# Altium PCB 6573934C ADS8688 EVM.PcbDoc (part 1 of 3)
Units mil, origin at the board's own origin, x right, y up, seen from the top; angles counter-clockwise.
Board outline 4100 x 2700 mil, 6 copper layers (L1_Analog, L2_GND, L3_AnalogPower, L4_DigPower, L5_GND, L6_Digital), stack 58.4 mil thick; 282 components, 187 nets, 719 pads, 318 vias.
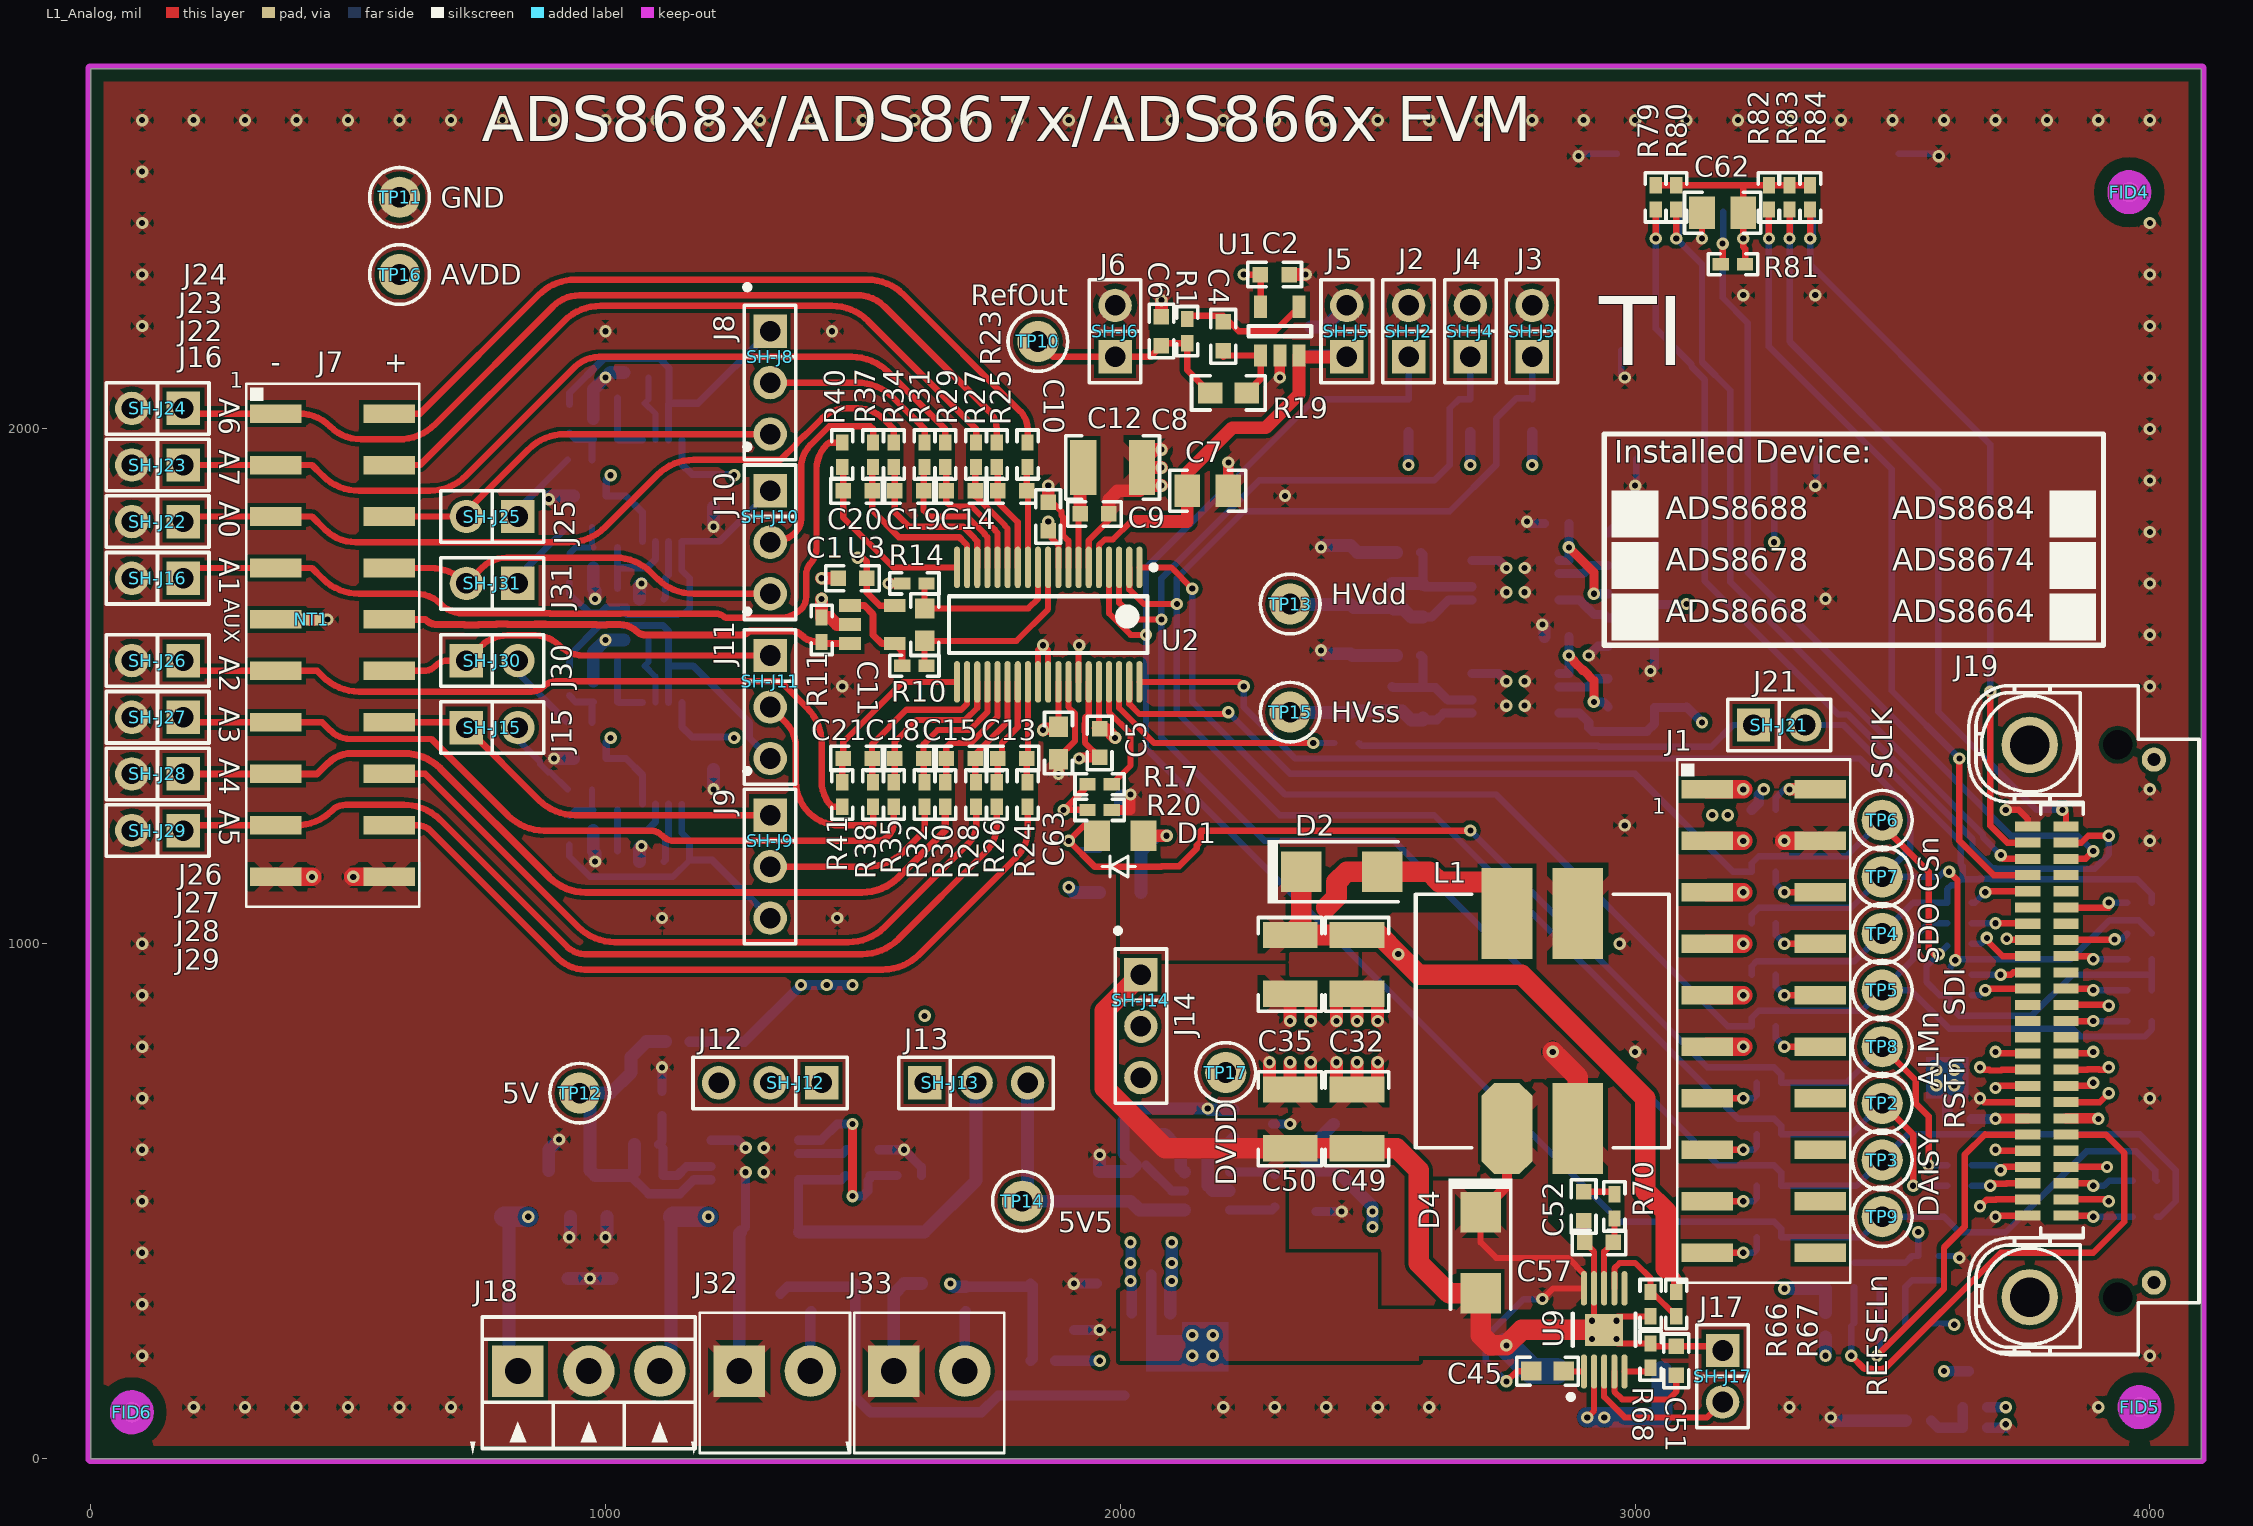
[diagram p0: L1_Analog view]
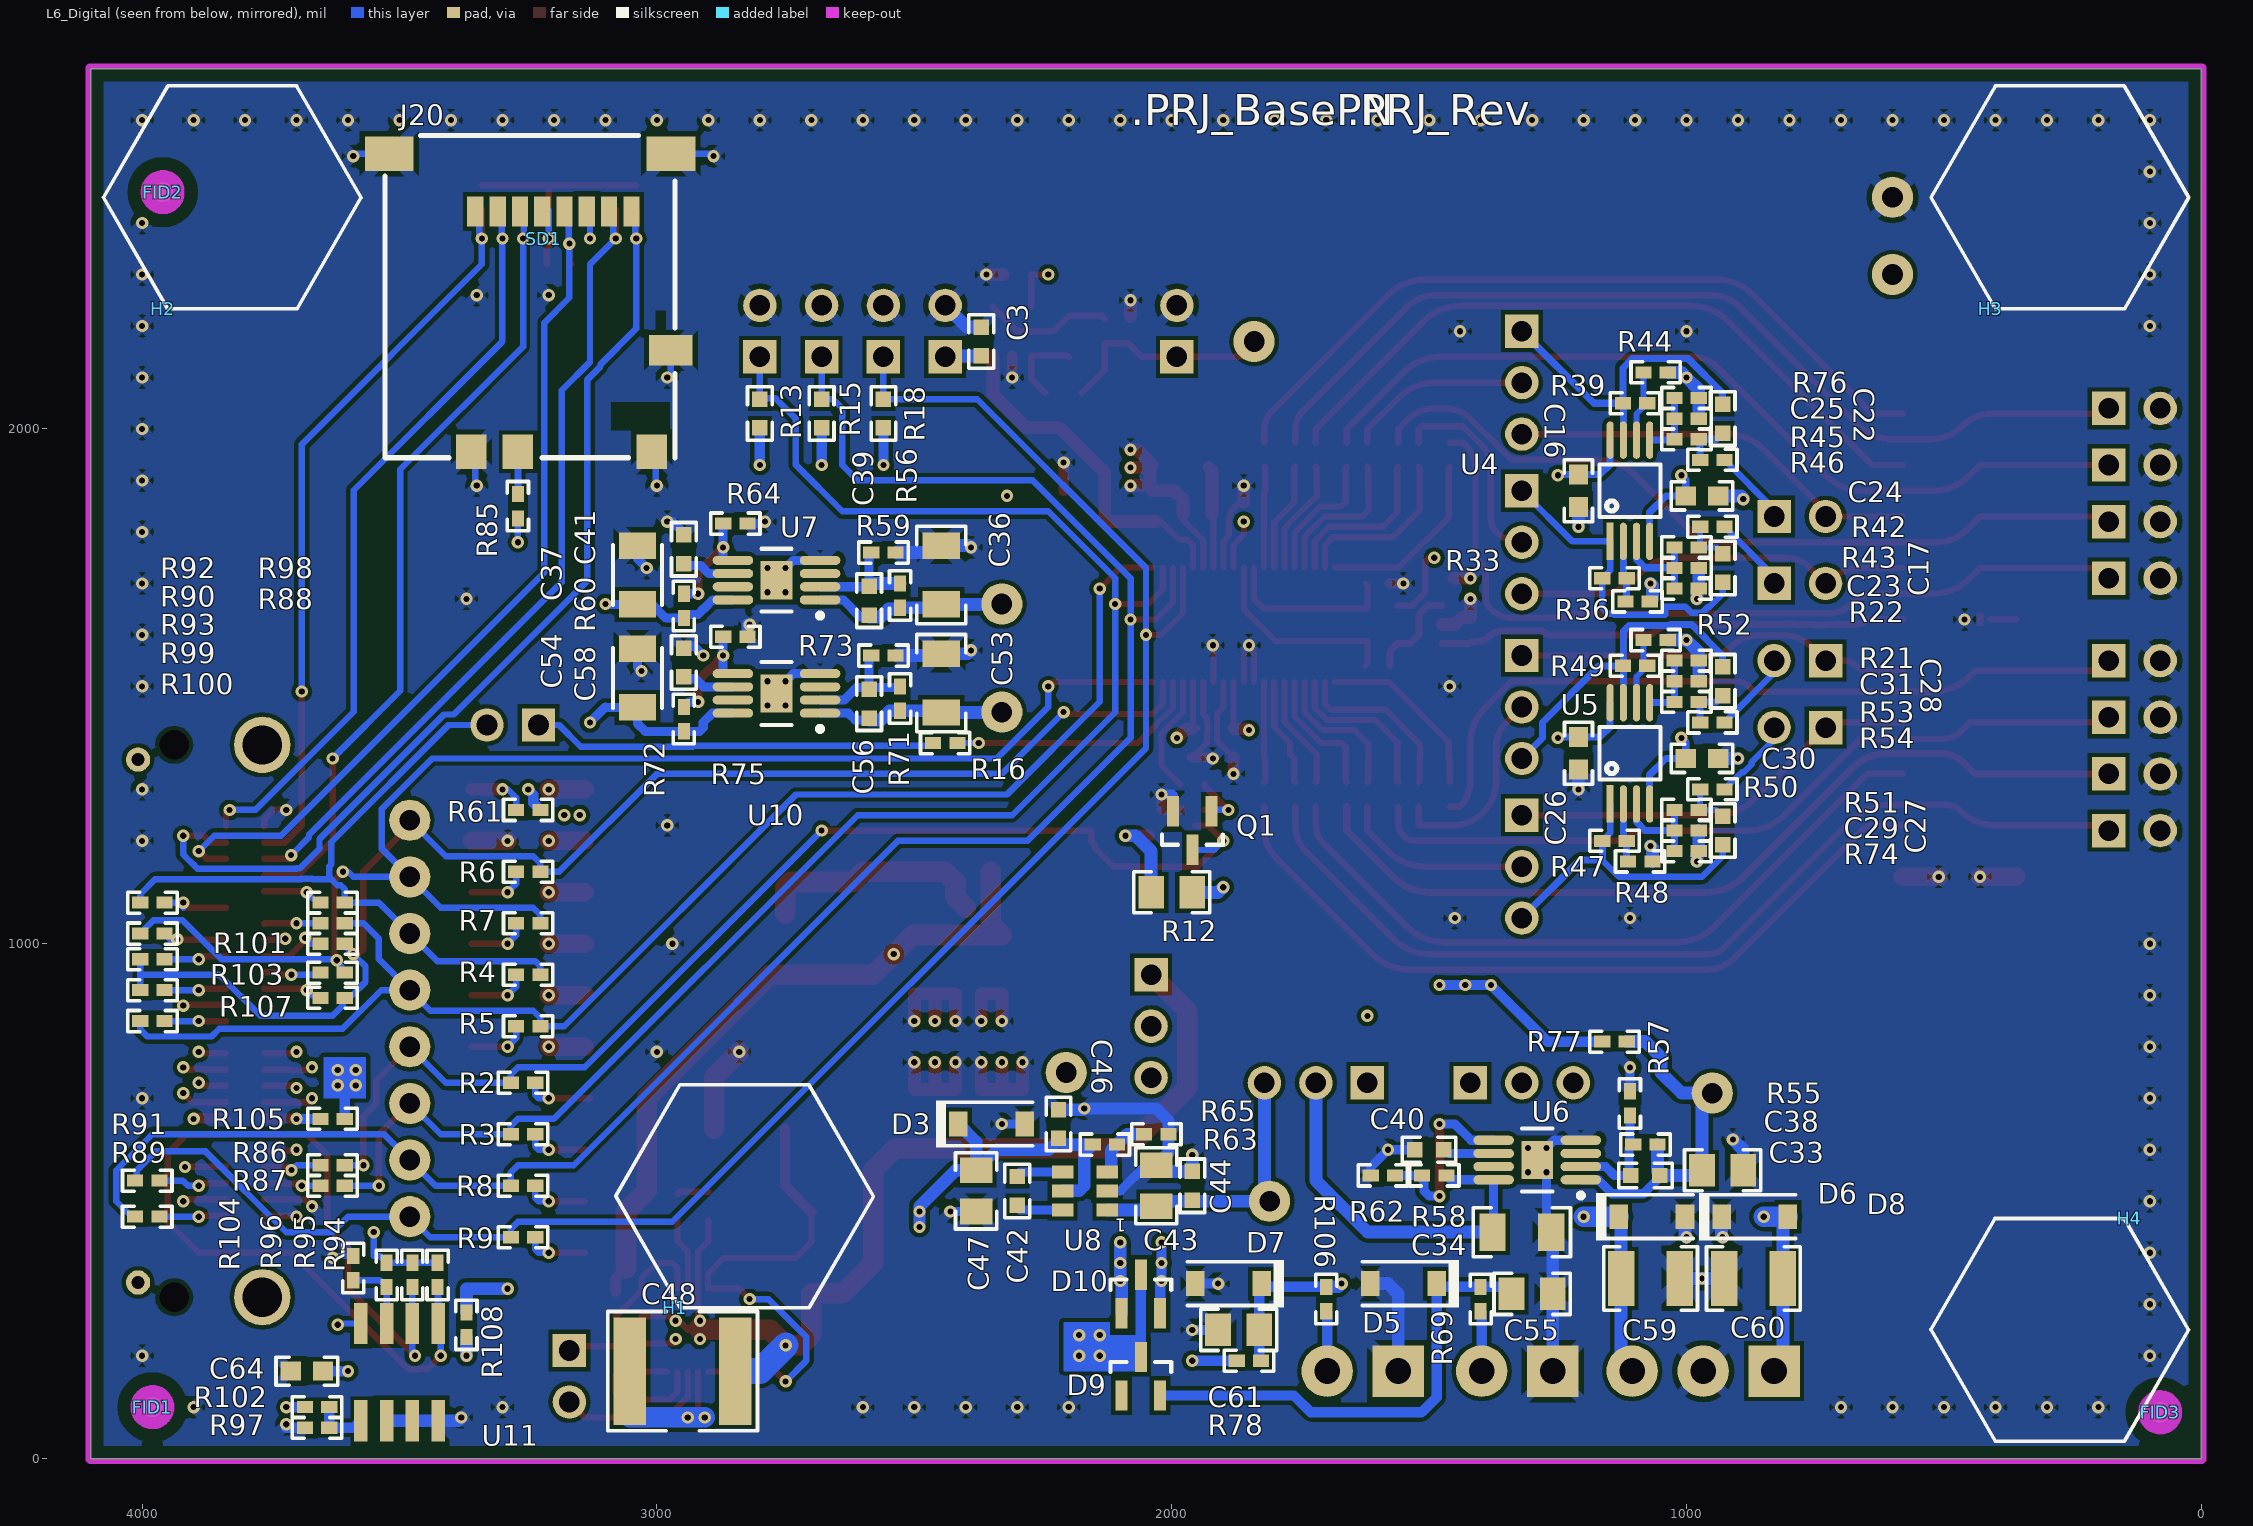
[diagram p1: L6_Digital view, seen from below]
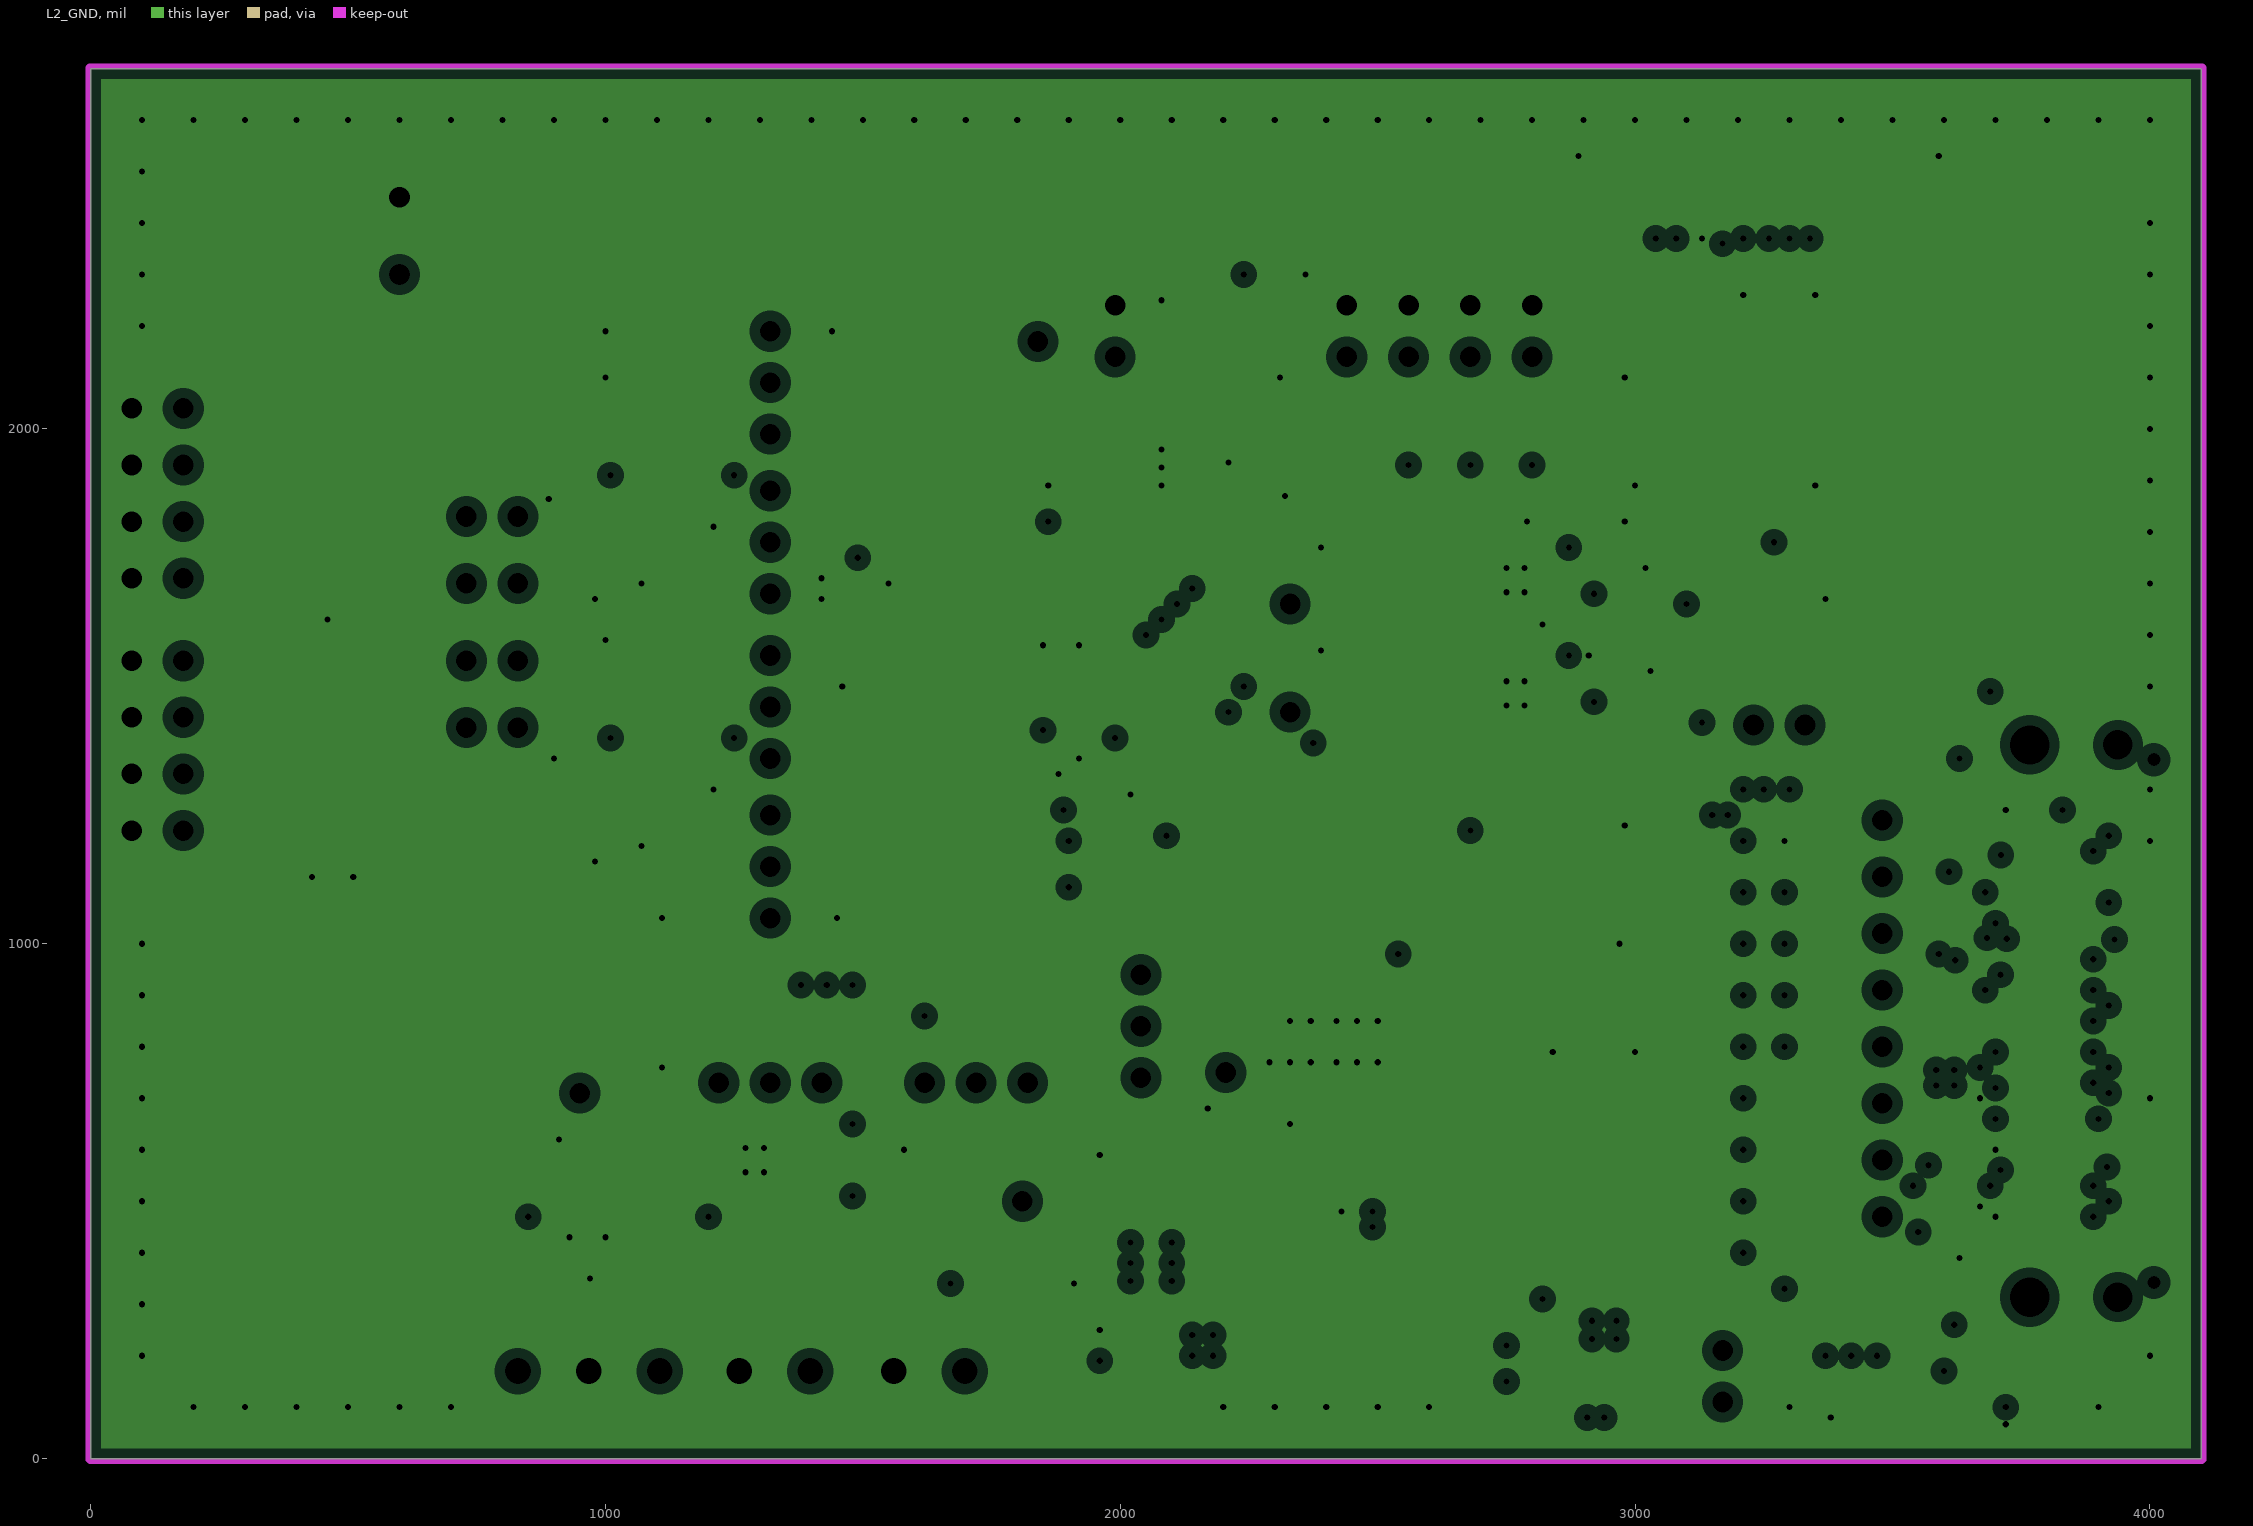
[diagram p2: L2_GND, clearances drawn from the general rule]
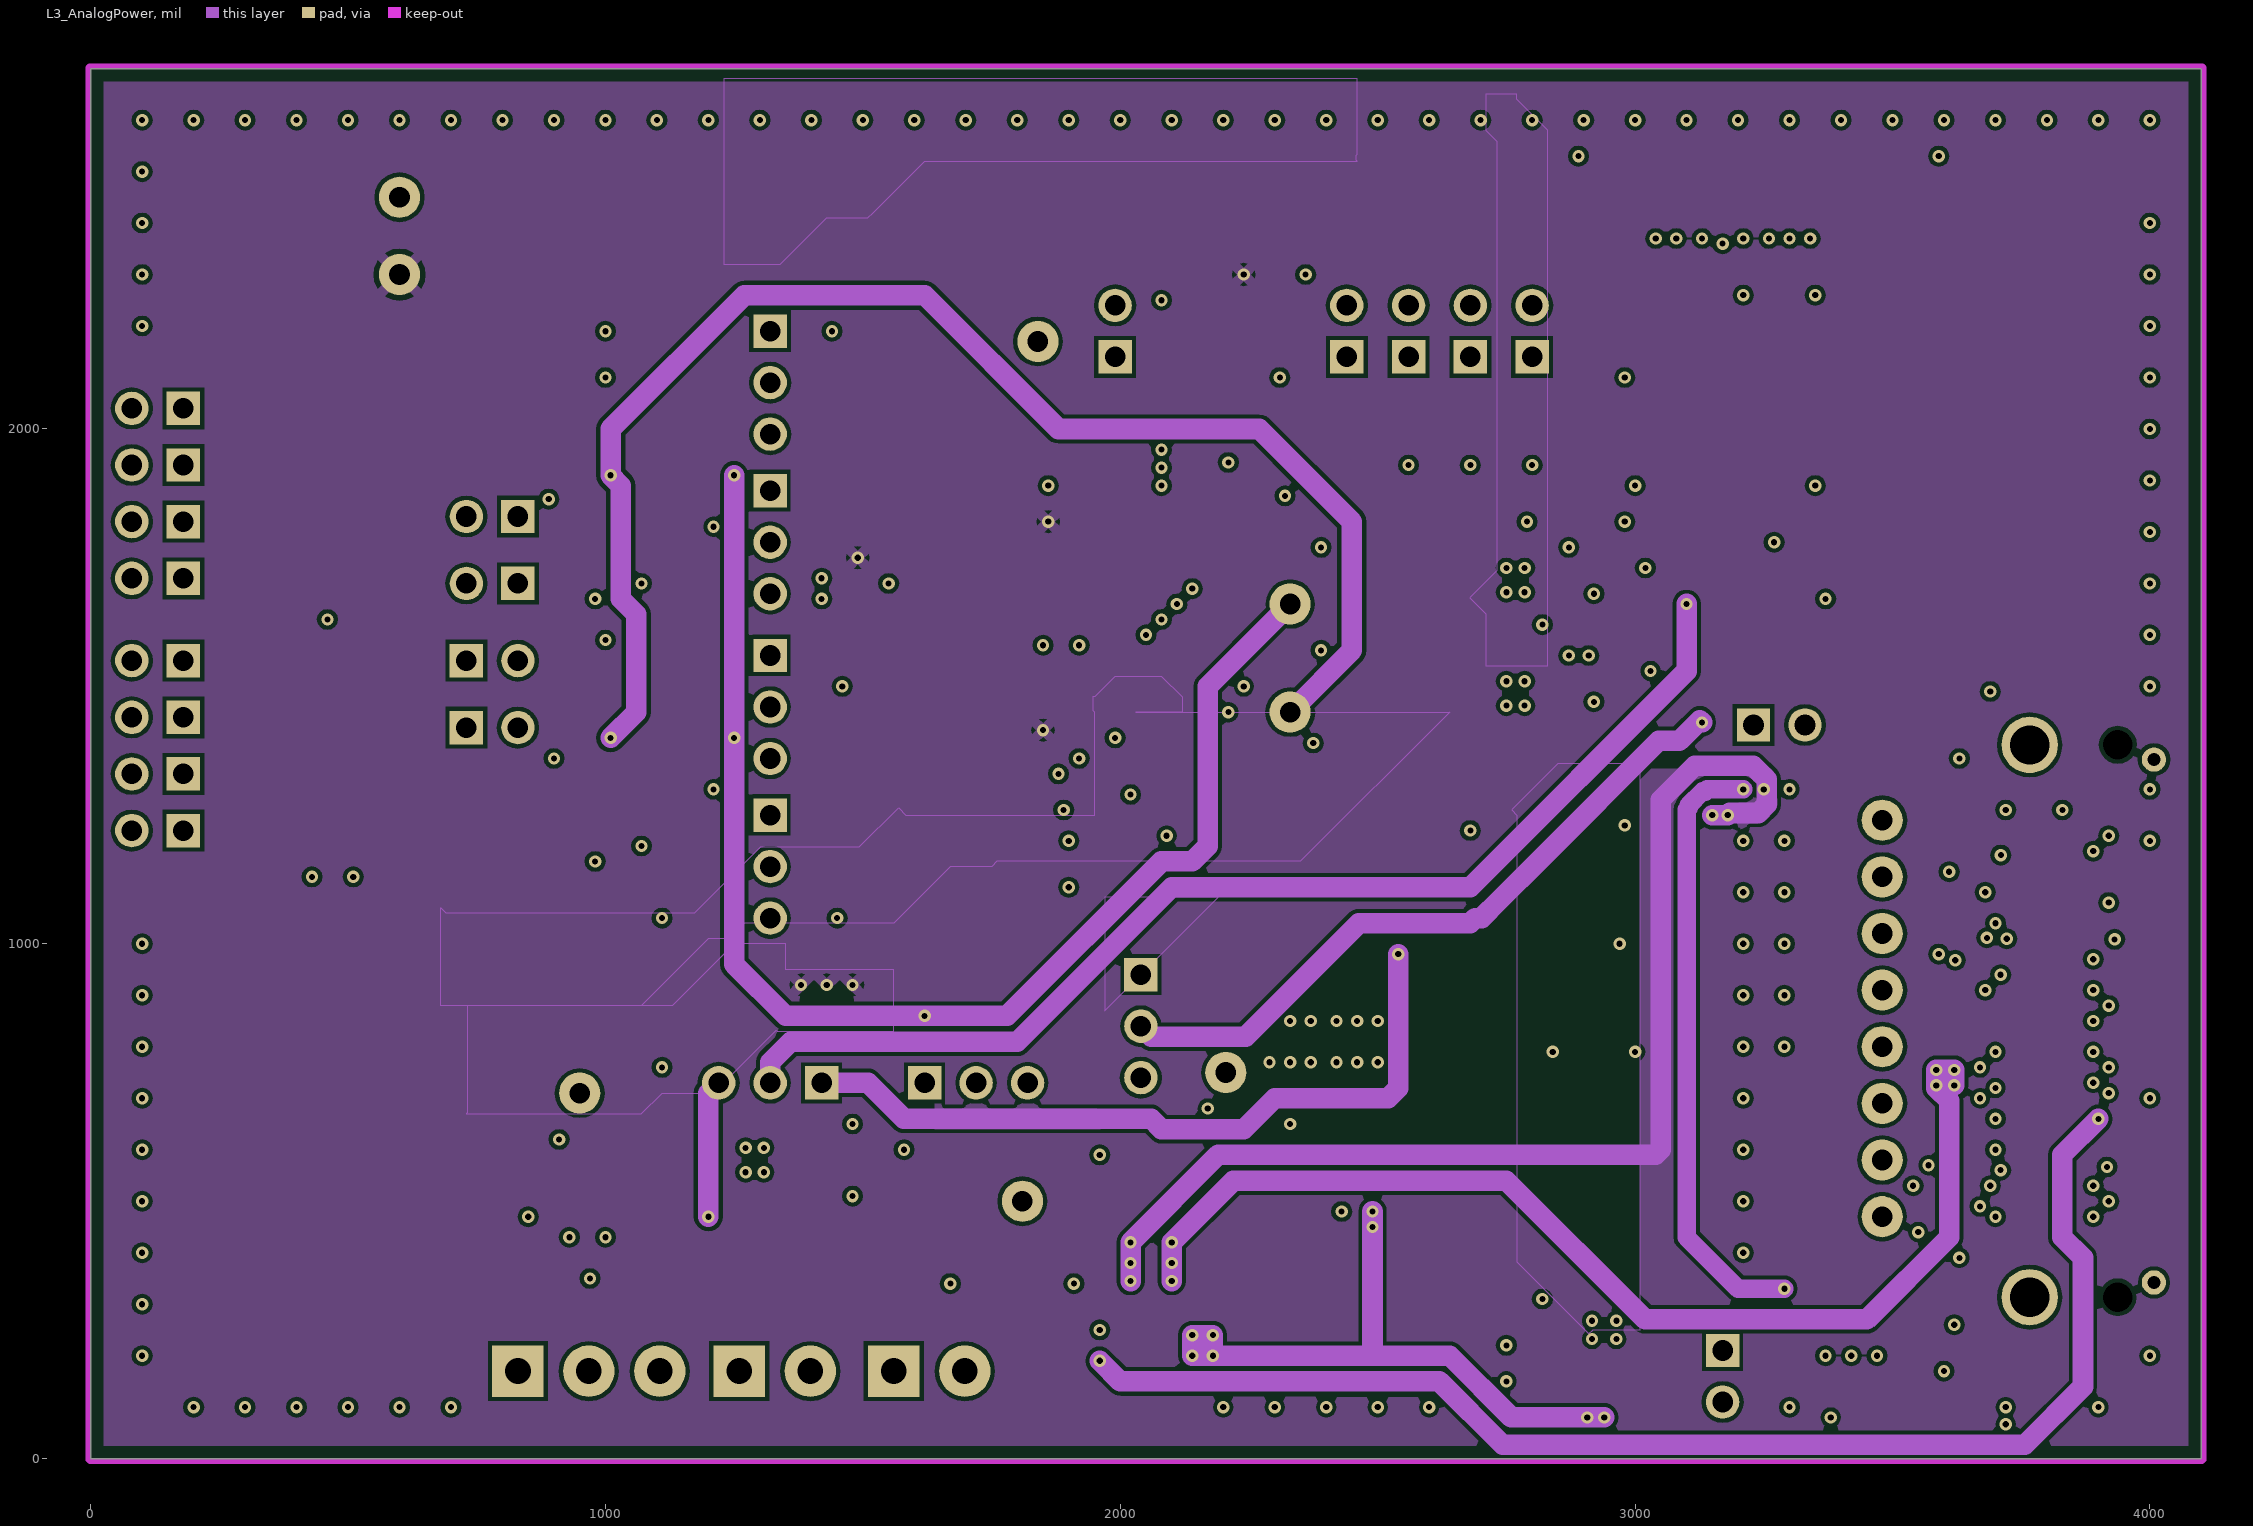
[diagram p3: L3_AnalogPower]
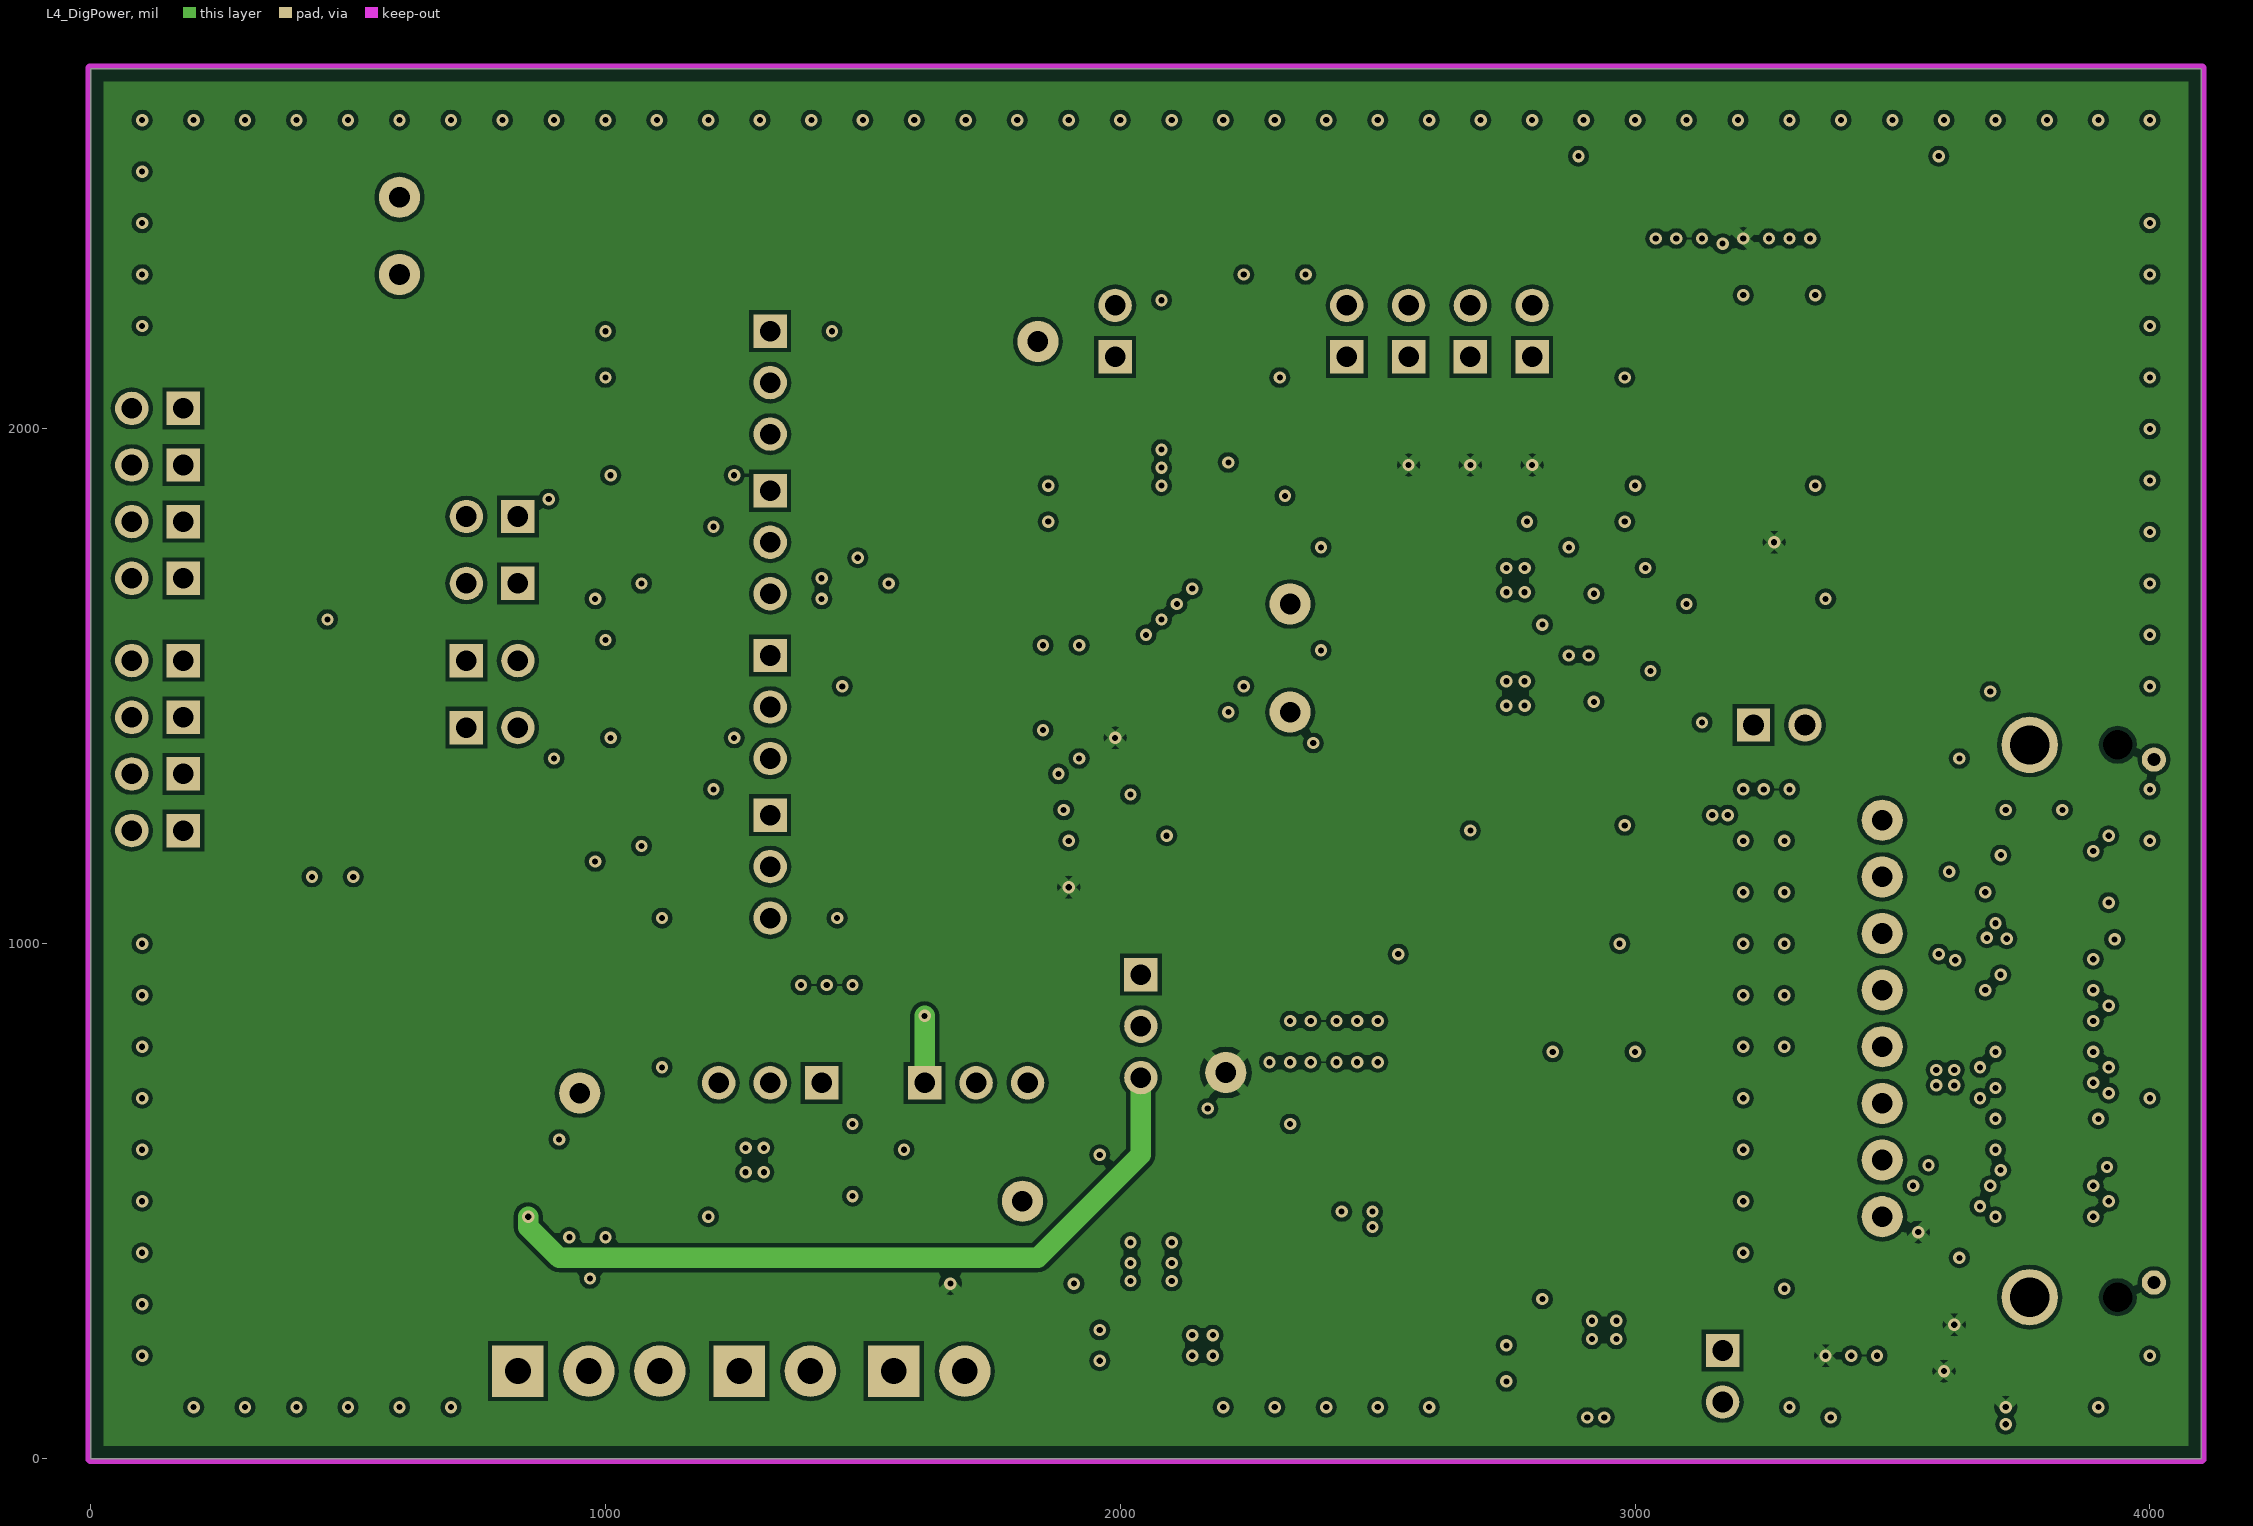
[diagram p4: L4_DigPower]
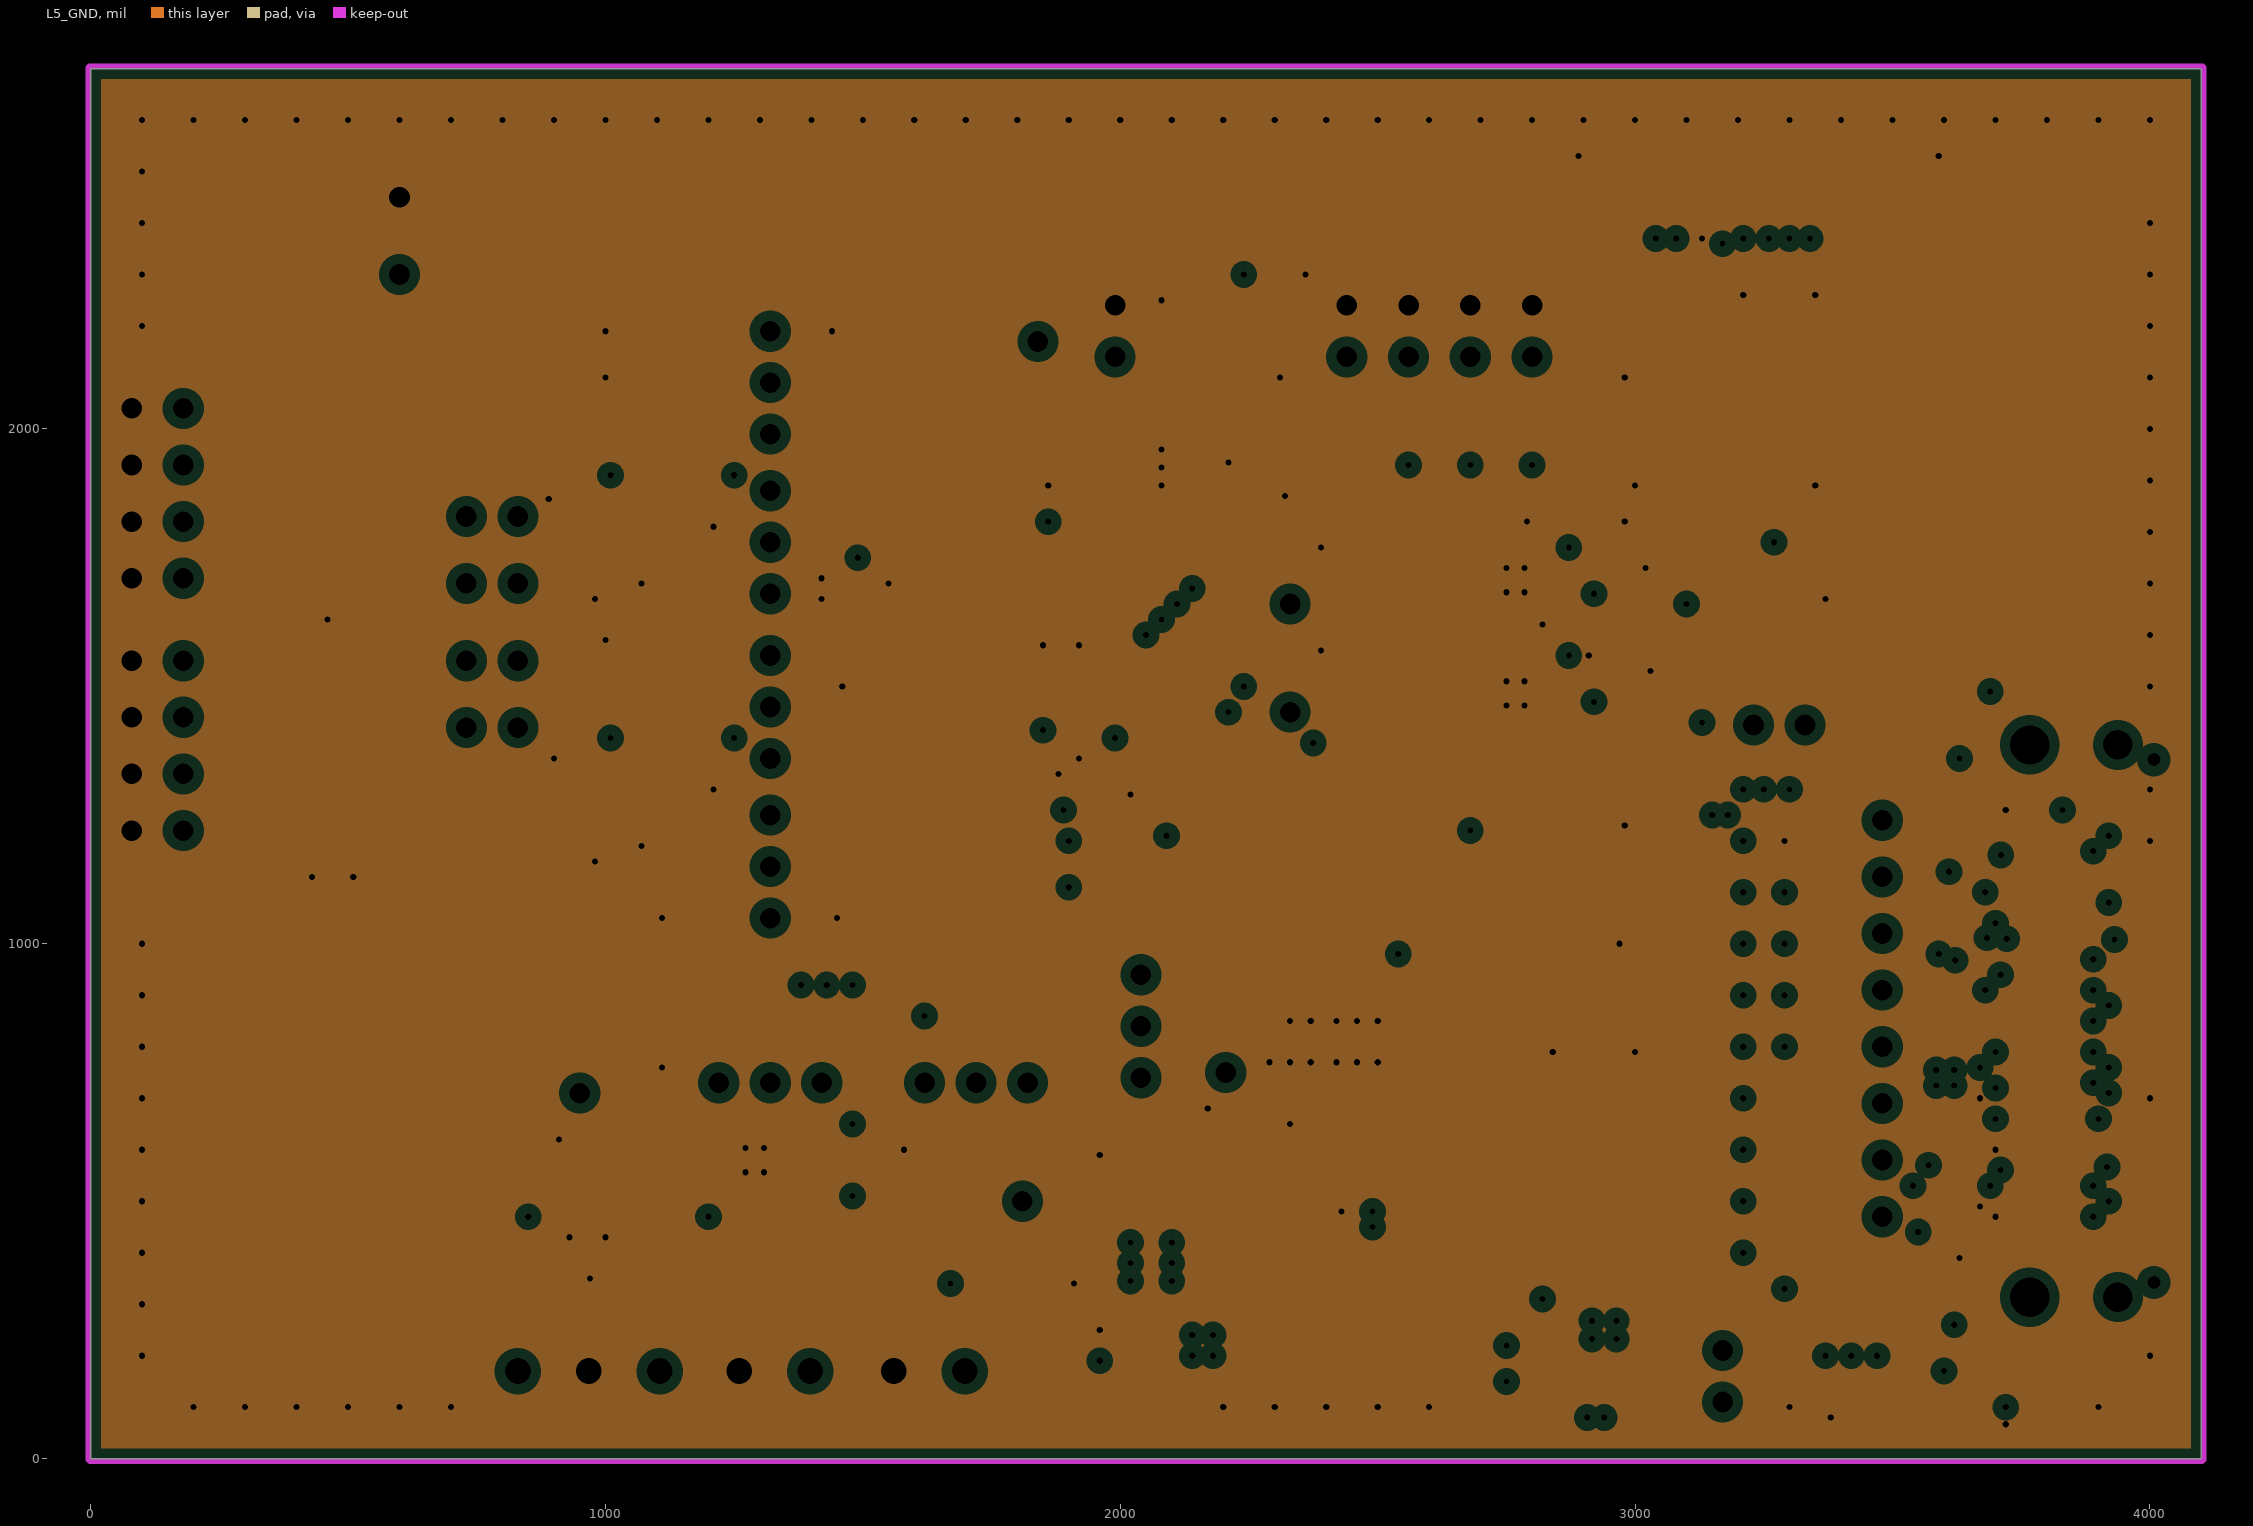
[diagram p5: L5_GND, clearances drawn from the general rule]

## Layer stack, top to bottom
L1_Analog: signal copper 1.4
Dielectric: core 8, FR-4, Dk 4.8
L2_GND: plane copper 1.4, net GND
Dielectric: prepreg 10, FR-4, Dk 4.8
L3_AnalogPower: signal copper 1.4
Dielectric: core 14, FR-4, Dk 4.8
L4_DigPower: signal copper 1.4
Dielectric: prepreg 10, FR-4, Dk 4.8
L5_GND: plane copper 1.4, net GND
Dielectric: core 8, FR-4, Dk 4.8
L6_Digital: signal copper 1.4

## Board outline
0,0 4100,0 4100,2700 0,2700

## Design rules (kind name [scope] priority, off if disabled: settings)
AcuteAngle [All] p1: minimum=4.00000000000000E+0001 checktracksonly=FALSE
AssemblyTestPointUsage [All] p1: valid=2
Clearance Clearance_BoardEdge_MountingHoles [OnCopper and InComponentClass('Mounting Holes') vs IsKeepOut] p1: gap=40
Clearance Clearance_BoardEdge_Poly [OnCopper and InPoly vs IsKeepOut] p2: gap=25
Clearance Clearance_BoardEdge [OnCopper and Not InComponentClass('Logo') and not InComponentClass('FiducialMark') and not InRegion(1000,500,4000,800) vs IsKeepOut] p3: gap=7
Clearance [All] p4: gap=7.87
ComponentClearance ComponentClearance_SMTConn [HasFootprint('0402*') or HasFootprint('0603*') or HasFootprint('0805*') or HasFootprint('1206*') vs HasFootprint('ERF8*')] p1: gap=10 collisioncheckmode=3 verticalgap=10 showdistances=FALSE // SMT Connectors With Mounting Holes
ComponentClearance ComponentClearance_Shunts [InComponentClass('Shunt')] p2: gap=0 collisioncheckmode=3 verticalgap=0 showdistances=FALSE
ComponentClearance ComponentClearance_Jumpers [HasFootprint('TSW-102-07-G-S') or HasFootprint('TSW-103-07-G-S')] p3: gap=-39.37 collisioncheckmode=3 verticalgap=10 showdistances=FALSE
ComponentClearance ComponentClearance_ScrewToNut [(HasFootprint('NY PMS 440 0025 PH')) vs (HasFootprint('Keystone_1902C'))] p4: gap=5 collisioncheckmode=3 verticalgap=10 showdistances=FALSE
ComponentClearance ComponentClearance_MountingHoles [InComponentClass('Mounting Holes')] p5: gap=250 collisioncheckmode=3 verticalgap=100000 showdistances=FALSE
ComponentClearance ComponentClearance_SmallPassives [HasFootprint('0201*') or HasFootprint('0402*') or HasFootprint('0508') or HasFootprint('0603*') or HasFootprint('0612') or HasFootprint('0805*') or HasFootprint('0815*') or HasFootprint('0830*') or HasFootprint('1206*') or HasFootprint('1210*') or HasFootprint('1808*') or HasFootprint('1812*') or HasFootprint('1825*') or HasFootprint('2010*') or HasFootprint('2220*') or HasFootprint('2225*') or HasFootprint('2512*') or HasFootprint('2728*') or HasFootprint('3518*') vs HasFootprint('0201*') or HasFootprint('0402*') or HasFootprint('0508') or HasFootprint('0603*') or HasFootprint('0612') or HasFootprint('0805*') or HasFootprint('0815*') or HasFootprint('0830*') or HasFootprint('1206*') or HasFootprint('1210*') or HasFootprint('1808*') or HasFootprint('1812*') or HasFootprint('1825*') or HasFootprint('2010*') or HasFootprint('2220*') or HasFootprint('2225*') or HasFootprint('2512*') or HasFootprint('2728*') or HasFootprint('3518*')] p6: gap=1 collisioncheckmode=3 verticalgap=10 showdistances=FALSE
ComponentClearance ComponentClearance_THtoSMT [IsThruComponent vs IsSMTComponent] p7: gap=7 collisioncheckmode=3 verticalgap=100000 showdistances=TRUE
ComponentClearance ComponentClearance_THtoTH [IsThruComponent vs IsThruComponent] p8: gap=5 collisioncheckmode=3 verticalgap=100000 showdistances=FALSE
ComponentClearance [All] p9 off: gap=40 collisioncheckmode=3 verticalgap=10 showdistances=FALSE
DiffPairsRouting [All] p1: maxlimit=100 minlimit=10 mostfreqgap=10 maxuncoupledlength=1000
FabricationTestPointUsage TestPointUsage [All] p1: valid=2 allowmultiple=FALSE
FabricationTestpoint Testpoint [All] p1: side=3 testpointundercomponent=TRUE minsize=40 maxsize=100 preferedsize=60 minholesize=0 maxholesize=40 preferedholesize=32 testpointgrid=1 allowsidetop=TRUE allowsidebottom=TRUE usegrid=TRUE gridtolerance=0.01
FanoutControl Fanout_LCC [IsLCC] p1: bgadir=Out bgaviamode=Centered fanoutstyle=Auto fanoutdirection=Alternating viagrid=1 // Fanout_LCC (Default Rule)
FanoutControl Fanout_BGA [IsBGA] p2: bgadir=Out bgaviamode=Centered fanoutstyle=Auto fanoutdirection=Alternating viagrid=1 // Fanout_BGA (Default Rule)
FanoutControl Fanout_Default [All] p4: bgadir=Out bgaviamode=Centered fanoutstyle=Auto fanoutdirection=Alternating viagrid=1 // Fanout_Default (Default Rule)
FanoutControl Fanout_Small [(CompPinCount < 5)] p5: bgadir=Out bgaviamode=Centered fanoutstyle=Auto fanoutdirection=OutThenIn viagrid=1 // Fanout_Small (Default Rule)
HoleSize [All] p1: absolutevalues=TRUE maxlimit=251 minlimit=8 maxpercent=80.000 minpercent=20.000
MinimumAnnularRing [All] p1: minimumring=4
MinimumSolderMaskSliver MinimumSolderMaskSliver_Logo [InComponentClass('Logo') vs InComponentClass('Logo')] p1: minsoldermaskwidth=0.7
MinimumSolderMaskSliver [All] p2: minsoldermaskwidth=1.8
PlaneClearance [All] p1: clearance=20
PlaneConnect PlaneConnect_VIAS [IsVia] p1: planeconnectstyle=Direct reliefexpansion=20 reliefentries=4 reliefconductorwidth=10 reliefairgap=10
PlaneConnect [All] p2: planeconnectstyle=Relief reliefexpansion=10 reliefentries=4 reliefconductorwidth=20 reliefairgap=10
PolygonConnect [All] p1: connectstyle=Relief reliefconductorwidth=20 reliefentries=4 polygonreliefangle="45 Angle" airgapwidth=10
RoutingVias [All] p1: holewidth=12 width=24 viastyle="Through Hole" minholewidth=8 minwidth=15 maxholewidth=40 maxwidth=65
SMDToCorner [All] p1: distance=0
SilkToSilkClearance [All] p1: silktosilkclearance=1
SilkscreenOverComponentPads [All] p1: minsilkscreentomaskgap=2
SolderMaskExpansion [All] p1: expansion=3
Width [All] p1: maxlimit=100 minlimit=6 preferedwidth=12.52 toplayer_minwidth=11.81 bottomlayer_minwidth=11.81 minimp=50.000000 maximp=50.000000 favimp=50.000000 checkconnectedcopper=TRUE
13 further rules are at their usual default settings.

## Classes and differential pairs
component class "6573934B ADC-OPA": AA1 C1 C2 C3 C4 C5 C6 C7 C8 C9 C10 C11 C12 C13 C14 C15 C16 C17 C18 C19 C20 C21 C22 C23 C24 C25 C26 C27 C28 C29 C30 C31 C63 D1 FID1 FID2 FID3 FID4 FID5 FID6 H1 H2 H3 H4 H5 H6 H7 H8 J1 J2 J3 J4 J5 J6 J7 J8 J9 J10 J11 J15 J16 J21 J22 J23 J24 J25 J26 J27 J28 J29 J30 J31 NT1 Q1 R1 R2 R3 R4 R5 R6 R7 R8 R9 R10 R11 R12 R13 R14 R15 R16 R17 R18 R19 R20 R21 R22 R23 R24 R25 R26 R27 R28 R29 R30 R31 R32 R33 R34 R35 R36 R37 R38 R39 R40 R41 R42 R43 R44 R45 R46 R47 R48 R49 R50 R51 R52 R53 R54 R74 R76 SD1 SH-J2 SH-J3 SH-J4 SH-J5 SH-J6 SH-J8 SH-J9 SH-J10 SH-J11 SH-J12 SH-J13 SH-J14 SH-J15 SH-J16 SH-J17 SH-J21 SH-J22 SH-J23 SH-J24 SH-J25 SH-J26 SH-J27 SH-J28 SH-J29 SH-J30 SH-J31 TP2 TP3 TP4 TP5 TP6 TP7 TP8 TP9 TP10 TP11 U1 U2 U3 U4 U5
component class "6573934B Power": C32 C33 C34 C35 C36 C37 C38 C39 C40 C41 C42 C43 C44 C45 C46 C47 C48 C49 C50 C51 C52 C53 C54 C55 C56 C57 C58 C59 C60 C61 C62 C64 D2 D3 D4 D5 D6 D7 D8 D9 D10 J12 J13 J14 J17 J18 J19 J20 J32 J33 L1 R55 R56 R57 R58 R59 R60 R61 R62 R63 R64 R65 R66 R67 R68 R69 R70 R71 R72 R73 R75 R77 R78 R79 R80 R81 R82 R83 R84 R85 R86 R87 R88 R89 R90 R91 R92 R93 R94 R95 R96 R97 R98 R99 R100 R101 R102 R103 R104 R105 R106 R107 R108 TP12 TP13 TP14 TP15 TP16 TP17 U6 U7 U8 U9 U10 U11
component class FiducialMark: FID1 FID2 FID3 FID4 FID5 FID6
component class Header: J2 J3 J4 J5 J6 J8 J9 J10 J11 J12 J13 J14 J15 J16 J17 J21 J22 J23 J24 J25 J26 J27 J28 J29 J30 J31
component class Shunt: SH-J2 SH-J3 SH-J4 SH-J5 SH-J6 SH-J8 SH-J9 SH-J10 SH-J11 SH-J12 SH-J13 SH-J14 SH-J15 SH-J16 SH-J17 SH-J21 SH-J22 SH-J23 SH-J24 SH-J25 SH-J26 SH-J27 SH-J28 SH-J29 SH-J30 SH-J31

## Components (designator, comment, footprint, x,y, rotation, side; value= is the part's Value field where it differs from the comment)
C1 "06033C104JAT2A" 0603_HV 1480,1710 r180 top
C2 "06033C104JAT2A" 0603_HV 2300,2300 r0 top
C3 "06033C104JAT2A" 0603_HV 2370,2170 r90 bottom
C4 "C1608C0G1H103J080AA" 0603_HV 2200,2180 r90 top
C5 "C0603C106M9PACTU" 0603_HV 1960,1390 r270 top
C6 "06033C104JAT2A" 0603_HV 2080,2190 r90 top
C7 "GRM21BR71A106KE51L" 0805_HV 2170,1880 r0 top
C8 "C3225X7R1C226M" 1210 1985,1925 r180 top
C9 "C1608X7R1C105K" 0603_HV 1950,1835 r180 top
C10 "C0603C105K4PACTU" 0603_HV 1860,1830 r270 top
C11 "GRM1885C1H302JA01D" 0603 1620,1620 r90 top
C12 "C1608C0G1H103J080AA" 0603_HV 1790,1880 r180 top
C13 "C1608C0G1H103J080AA" 0603_HV 1790,1360 r180 top
C14 "C1608C0G1H103J080AA" 0603_HV 1690,1880 r180 top
C15 "C1608C0G1H103J080AA" 0603_HV 1690,1360 r180 top
C16 "06035C104KAT2A" 0603 1210,1880 r90 bottom
C17 "C1608C0G1H222J" 0603_HV 930,1730 r90 bottom
C18 "C1608C0G1H103J080AA" 0603_HV 1590,1360 r180 top
C19 "C1608C0G1H103J080AA" 0603_HV 1590,1880 r180 top
C20 "C1608C0G1H103J080AA" 0603_HV 1490,1880 r180 top
C21 "C1608C0G1H103J080AA" 0603_HV 1490,1360 r180 top
C22 "C1608C0G1H222J" 0603_HV 930,2020 r270 bottom
C23 "GRM1555C1H102JA01D" 0402 1000,1730 r180 bottom
C24 "06035C104KAT2A" 0603 970,1870 r0 bottom
C25 "GRM1555C1H102JA01D" 0402 1000,2020 r180 bottom
C26 "06035C104KAT2A" 0603 1210,1370 r270 bottom
C27 "C1608C0G1H222J" 0603_HV 930,1220 r90 bottom
C28 "C1608C0G1H222J" 0603_HV 930,1510 r270 bottom
C29 "GRM1555C1H102JA01D" 0402 1000,1220 r180 bottom
C30 "06035C104KAT2A" 0603 970,1360 r180 bottom
C31 "GRM1555C1H102JA01D" 0402 1000,1510 r180 bottom
C32 "GRM32ER71E226KE15L" 1210 2460,960 r270 top
C33 "GRM21BR71A106KE51L" 0805_HV 930,560 r180 bottom
C34 "GRM31CR71E106KA12L" 1206 1320,440 r180 bottom
C35 "GRM32ER71E226KE15L" 1210 2330,960 r270 top
C36 "GRM31CR71E106KA12L" 1206 2447.72,1716.38 r90 bottom
C37 "GMK316AB7106KL" 1206 3037.72,1716.38 r90 bottom
C38 "C1608C0G1H103J080AA" 0603_HV 1080,550 r0 bottom
C39 "C1608C0G1H103J080AA" 0603_HV 2587.72,1666.38 r90 bottom
C40 "C1608C0G1H103J080AA" 0603_HV 1500,600 r0 bottom
C41 "C1608C0G1H103J080AA" 0603_HV 2947.72,1766.38 r90 bottom
C42 "C1608X7R1C224K" 0603_HV 2300,520 r90 bottom
C43 "GRM21BR71A106KE51L" 0805_HV 2030,530 r90 bottom
C44 "GRM188R71A225KE15D" 0603_HV 1960,530 r90 bottom
C45 "06035C104KAT2A" 0603 2830,170 r0 top
C46 "GRM188R71A225KE15D" 0603_HV 2220,650 r90 bottom
C47 "GRM21BR71A106KE51L" 0805_HV 2380,520 r270 bottom
C48 "C5750X7R1H106M" 2220 2950,170 r180 bottom locked
C49 "GRM32ER71E226KE15L" 1210 2460,660 r270 top
C50 "GRM32ER71E226KE15L" 1210 2330,660 r270 top
C51 "C0603C104J3RAC" 0603_HV 3080,190 r270 top locked
C52 "GRM188R71C394KA88D" 0603_HV 2900,490 r270 top locked
C53 "GRM31CR71E106KA12L" 1206 2447.72,1506.38 r90 bottom
C54 "GMK316AB7106KL" 1206 3037.72,1516.38 r90 bottom
C55 "GRM21BR71A106KE51L" 0805_HV 1300,320 r180 bottom
C56 "C1608C0G1H103J080AA" 0603_HV 2587.72,1466.38 r90 bottom
C57 "C1608X7R1H471K" 0603_HV 2930,420 r180 top locked
C58 "C1608C0G1H103J080AA" 0603_HV 2947.72,1546.38 r90 bottom
C59 "GRM32ER7YA106KA12L" 1210 1070,350 r0 bottom
C60 "GRM32ER7YA106KA12L" 1210 870,350 r0 bottom
C61 "GRM21BR71A106KE51L" 0805_HV 1870,250 r0 bottom
C62 "GRM21BR71A106KE51L" 0805_HV 3170,2420 r180 top
C63 "C1608X7R1C105K" 0603 1880,1390 r270 top
C64 "06035C104KAT2A" 0603 3680,170 r0 bottom
D1 "D-LTST-C170UKT" LED_0805 2000,1210 r0 top
D2 "B260A-13-F" SMA 2430,1140 r0 top locked
D3 "MMSZ4690T1G" SOD-123 2350,650 r180 bottom
D4 "B260A-13-F" SMA 2700,400 r270 top
D5 "MMSZ4690T1G" SOD-123 1550,340 r0 bottom
D6 "MMSZ4711-V" SOD-123 1067.55,470 r180 bottom
D7 "MMSZ4686T1G" SOD-123 1890,340 r0 bottom
D8 "MMSZ4711-V" SOD-123 867.61,470 r180 bottom
D9 "BAT54C-7-F" SOT-23 2060,160 r90 bottom
D10 "BAT54C-7-F" SOT-23 2060,320 r90 bottom
FID1 "Fiducial" Fiducial10-20 3980,100 r180 bottom
FID2 "Fiducial" Fiducial10-20 3960,2460 r180 bottom
FID3 "Fiducial" Fiducial10-20 80,90 r180 bottom
FID4 "Fiducial" Fiducial10-20 3960,2460 r0 top
FID5 "Fiducial" Fiducial10-20 3980,100 r0 top
FID6 "Fiducial" Fiducial10-20 80,90 r0 top
H1 "SJ5202" BUMPON_SJ5202 2830,510 r180 bottom locked
H2 "SJ5202" BUMPON_SJ5202 3825,2450 r180 bottom locked
H3 "SJ5202" BUMPON_SJ5202 275,2450 r180 bottom locked
H4 "SJ5202" BUMPON_SJ5202 275,250 r0 bottom locked
J1 "TSM-110-01-T-DV-P" CONN_TSM-110-01-T-DV-P 3250,850 r270 top locked
J2 "TSW-102-07-G-S" TSW-102-07-G-S 2560,2190 r90 top
J3 "TSW-102-07-G-S" TSW-102-07-G-S 2800,2190 r90 top
J4 "TSW-102-07-G-S" TSW-102-07-G-S 2680,2190 r90 top
J5 "TSW-102-07-G-S" TSW-102-07-G-S 2440,2190 r90 top
J6 "TSW-102-07-G-S" TSW-102-07-G-S 1990,2190 r90 top
J7 "TSM-110-01-T-DV-P" CONN_TSM-110-01-T-DV-P 470,1580 r270 top
J8 "TSW-103-07-G-S" TSW-103-07-G-S 1320,2090 r270 top
J9 "TSW-103-07-G-S" TSW-103-07-G-S 1320,1150 r270 top
J10 "TSW-103-07-G-S" TSW-103-07-G-S 1320,1780 r270 top
J11 "TSW-103-07-G-S" TSW-103-07-G-S 1320,1460 r270 top
J12 "TSW-103-07-G-S" TSW-103-07-G-S 1320,730 r180 top
J13 "TSW-103-07-G-S" TSW-103-07-G-S 1720,730 r0 top
J14 "TSW-103-07-G-S" TSW-103-07-G-S 2040,840 r270 top
J15 "TSW-102-07-G-S" TSW-102-07-G-S 780,1420 r0 top
J16 "TSW-102-07-G-S" TSW-102-07-G-S 130,1710 r180 top
J17 "TSW-102-07-G-S" TSW-102-07-G-S 3170,160 r270 top
J18 "ED555/3DS" TERM_BLK_ED555-3DS 830,170 r0 top
J19 "ERF8-025-01-L-D-RA-L-TR" ERF8-025-01-L-D-RA-L 3800,850 r270 top locked
J20 "502570-0893" MOLEX_502570-0893 3520,2570 r180 bottom
J21 "TSW-102-07-G-S" TSW-102-07-G-S 3280,1425 r0 top
J22 "TSW-102-07-G-S" TSW-102-07-G-S 130,1820 r180 top
J23 "TSW-102-07-G-S" TSW-102-07-G-S 130,1930 r180 top
J24 "TSW-102-07-G-S" TSW-102-07-G-S 130,2040 r180 top
J25 "TSW-102-07-G-S" TSW-102-07-G-S 780,1830 r180 top
J26 "TSW-102-07-G-S" TSW-102-07-G-S 130,1550 r180 top
J27 "TSW-102-07-G-S" TSW-102-07-G-S 130,1440 r180 top
J28 "TSW-102-07-G-S" TSW-102-07-G-S 130,1330 r180 top
J29 "TSW-102-07-G-S" TSW-102-07-G-S 130,1220 r180 top
J30 "TSW-102-07-G-S" TSW-102-07-G-S 780,1550 r0 top
J31 "TSW-102-07-G-S" TSW-102-07-G-S 780,1700 r180 top
J32 "ED555/2DS" TERM_BLK_ED555-2DS 1260,170 r0 top
J33 "ED555/2DS" TERM_BLK_ED555-2DS 1560,170 r0 top
L1 "744870471" 1280 2820,850 r180 top
NT1 "Net-Tie" Net-Tie_10mil 430,1630 r180 top net-tie
Q1 "BC847CLT1G" SOT-23 1960,1220 r270 bottom
R1 "CRCW040210K0FKED" 0402 2130,2190 r270 top
R2 "CRCW040249R9FKED" 0402 3260,730 r180 bottom
R3 "CRCW040249R9FKED" 0402 3260,630 r180 bottom
R4 "RC0402JR-070RL" 0402 3250,940 r0 bottom
R5 "CRCW040249R9FKED" 0402 3250,840 r0 bottom
R6 "CRCW040249R9FKED" 0402 3250,1140 r0 bottom
R7 "CRCW040249R9FKED" 0402 3250,1040 r0 bottom
R8 "CRCW040249R9FKED" 0402 3260,530 r180 bottom
R9 "CRCW040249R9FKED" 0402 3260,430 r180 bottom
R10 "CRCW040249R9FKED" 0402 1600,1540 r0 top
R11 "CRCW040210M0FKED" 0402 1420,1610 r270 top
R12 "CRCW08051K00JNEA" 0805_HV 2000,1100 r180 bottom
R13 "RC0603FR-0747KL" 0603_HV 2800,2030 r90 bottom
R14 "CRCW040249R9FKED" 0402 1600,1700 r0 top
R15 "RC0603FR-0747KL" 0603_HV 2680,2030 r90 bottom
R16 "CRCW040249R9FKED" 0402 2440,1390 r0 bottom
R17 "CRCW0402220KJNED" 0402 1960,1310 r0 top
R18 "RC0603FR-0747KL" 0603_HV 2560,2030 r90 bottom
R19 "CRCW0603100RFKEA" 0603M 2210,2070 r0 top
R20 "CRCW0402100KFKED" 0402 1960,1260 r180 top
R21 "CRCW040210M0FKED" 0402 1000,1550 r0 bottom
R22 "CRCW040210M0FKED" 0402 1000,1690 r0 bottom
R23 "CRCW0402357RFKED" 0402 1820,1950 r270 top
R24 "CRCW0402357RFKED" 0402 1820,1290 r270 top
R25 "CRCW0402357RFKED" 0402 1760,1950 r270 top
R26 "CRCW0402357RFKED" 0402 1760,1290 r270 top
R27 "CRCW0402357RFKED" 0402 1720,1950 r270 top
R28 "CRCW0402357RFKED" 0402 1720,1290 r270 top
R29 "CRCW0402357RFKED" 0402 1660,1950 r270 top
R30 "CRCW0402357RFKED" 0402 1660,1290 r270 top
R31 "CRCW0402357RFKED" 0402 1620,1950 r270 top
R32 "CRCW0402357RFKED" 0402 1620,1290 r270 top
R33 "RC0402JR-070RL" 0402 1140,1710 r0 bottom
R34 "CRCW0402357RFKED" 0402 1560,1950 r270 top
R35 "CRCW0402357RFKED" 0402 1560,1290 r270 top
R36 "NI" "0402 - UN" 1095,1665 r0 bottom
R37 "CRCW0402357RFKED" 0402 1520,1950 r270 top
R38 "CRCW0402357RFKED" 0402 1520,1290 r270 top
R39 "RC0402JR-070RL" 0402 1100,2050 r0 bottom
R40 "CRCW0402357RFKED" 0402 1460,1950 r270 top
R41 "CRCW0402357RFKED" 0402 1460,1290 r270 top
R42 "CRCW04023K57FKED" 0402 950,1810 r0 bottom
R43 "CRCW04026K65FKED" 0402 1000,1770 r0 bottom
R44 "NI" "0402 - UN" 1060,2110 r0 bottom
R45 "CRCW04026K65FKED" 0402 1000,1980 r180 bottom
R46 "CRCW04023K57FKED" 0402 950,1940 r180 bottom
R47 "RC0402JR-070RL" 0402 1140,1200 r0 bottom
R48 "NI" "0402 - UN" 1090,1160 r180 bottom
R49 "RC0402JR-070RL" 0402 1100,1540 r0 bottom
R50 "CRCW04023K57FKED" 0402 950,1300 r0 bottom
R51 "CRCW04026K65FKED" 0402 1000,1260 r0 bottom
R52 "NI" "0402 - UN" 1060,1590 r180 bottom
R53 "CRCW04026K65FKED" 0402 1000,1470 r180 bottom
R54 "CRCW04023K57FKED" 0402 950,1430 r180 bottom
R55 "CRCW0402576KFKED" 0402 1080,610 r180 bottom
R56 "CRCW0402232KFKED" 0402 2527.72,1676.38 r270 bottom
R57 "CRCW0402182KFKED" 0402 1110,690 r90 bottom
R58 "CRCW0402499KFKED" 0402 1490,550 r180 bottom
R59 "CRCW040220K0JNED" 0402 2560,1760 r0 bottom
R60 "CRCW0402499KFKED" 0402 2947.72,1656.38 r270 bottom
R61 "RC0402JR-070RL" 0402 3250,1260 r0 bottom
R62 "CRCW0402499KFKED" 0402 1590,550 r0 bottom
R63 "CRCW040233K0JNED" 0402 2130,610 r180 bottom
R64 "CRCW040282K0JNED" 0402 2847.72,1816.38 r0 bottom
R65 "CRCW040215K0JNED" 0402 2030,630 r180 bottom
R66 "CRCW04021K10JNED" 0402 3030,300 r90 top locked
R67 "CRCW040244K2FKED" 0402 3080,300 r90 top locked
R68 "CRCW0402412KFKED" 0402 3030,200 r270 top locked
R69 "RC0402JR-070RL" 0402 1400,310 r90 bottom
R70 "CRCW040220K5FKED" 0402 2960,490 r270 top locked
R71 "CRCW0402232KFKED" 0402 2527.72,1476.38 r270 bottom
R72 "CRCW0402499KFKED" 0402 2947.72,1436.38 r270 bottom
R73 "CRCW040220K0JNED" 0402 2560,1560 r0 bottom
R74 "CRCW040210M0FKED" 0402 1000,1180 r0 bottom
R75 "CRCW040282K0JNED" 0402 2847.72,1596.38 r0 bottom
R76 "CRCW040210M0FKED" 0402 1000,2060 r0 bottom
R77 "RC0402JR-070RL" 0402 1140,810 r180 bottom
R78 "RC0402JR-070RL" 0402 1850,190 r180 bottom
R79 "CRCW040210K0FKED" 0402 3040,2450 r90 top
R80 "CRCW040210K0FKED" 0402 3080,2450 r90 top
R81 "CRCW040210K0FKED" 0402 3190,2320 r0 top
R82 "CRCW040210K0FKED" 0402 3260,2450 r90 top
R83 "CRCW040210K0FKED" 0402 3300,2450 r90 top
R84 "CRCW040210K0FKED" 0402 3340,2450 r90 top
R85 "CRCW040210K0FKED" 0402 3270,1850 r270 bottom
R86 "CRCW040249R9FKED" 0402 3630,570 r180 bottom
R87 "CRCW040249R9FKED" 0402 3630,530 r180 bottom
R88 "CRCW040249R9FKED" 0402 3630,1040 r180 bottom
R89 "CRCW040249R9FKED" 0402 3990,470 r180 bottom
R90 "CRCW040249R9FKED" 0402 3980,1020 r180 bottom
R91 "CRCW040249R9FKED" 0402 3990,540 r180 bottom
R92 "RC0402JR-070RL" 0402 3980,1080 r180 bottom
R93 "CRCW040249R9FKED" 0402 3980,970 r180 bottom
R94 "NI" "0402 - UN" 3426,357 r270 bottom
R95 "NI" "0402 - UN" 3475,357 r270 bottom
R96 "NI" "0402 - UN" 3525,357 r270 bottom
R97 "RC0402JR-070RL" 0402 3660,60 r0 bottom
R98 "NI" "0402 - UN" 3630,1080 r180 bottom
R99 "NI" "0402 - UN" 3980,910 r180 bottom
R100 "NI" "0402 - UN" 3980,850 r180 bottom
R101 "RC0402JR-070RL" 0402 3630,1000 r180 bottom
R102 "NI" "0402 - UN" 3660,100 r180 bottom
R103 "NI" "0402 - UN" 3630,944 r180 bottom
R104 "RC0402JR-070RL" 0402 3590,370 r90 bottom
R105 "RC0402JR-070RL" 0402 3630,660 r180 bottom
R106 "RC0402JR-070RL" 0402 1700,310 r90 bottom
R107 "NI" "0402 - UN" 3630,895 r180 bottom
R108 "RC0402JR-070RL" 0402 3370,260 r270 bottom
SD1 "SDSDQ-002G" MicroSD 3220,2370 r270 bottom
SH-J2 "969102-0000-DA" SNT-100-BK-G 2560,2190 r90 top
SH-J3 "969102-0000-DA" SNT-100-BK-G 2800,2190 r90 top
SH-J4 "969102-0000-DA" SNT-100-BK-G 2680,2190 r90 top
SH-J5 "969102-0000-DA" SNT-100-BK-G 2440,2190 r90 top
SH-J6 "969102-0000-DA" SNT-100-BK-G 1990,2190 r90 top
SH-J8 "969102-0000-DA" SNT-100-BK-G 1320,2140 r90 top
SH-J9 "969102-0000-DA" SNT-100-BK-G 1320,1200 r90 top
SH-J10 "969102-0000-DA" SNT-100-BK-G 1320,1830 r90 top
SH-J11 "969102-0000-DA" SNT-100-BK-G 1320,1510 r90 top
SH-J12 "969102-0000-DA" SNT-100-BK-G 1370,730 r0 top
SH-J13 "969102-0000-DA" SNT-100-BK-G 1670,730 r180 top
SH-J14 "969102-0000-DA" SNT-100-BK-G 2040,890 r90 top
SH-J15 "969102-0000-DA" SNT-100-BK-G 780,1420 r180 top
SH-J16 "969102-0000-DA" SNT-100-BK-G 130,1710 r180 top
SH-J17 "969102-0000-DA" SNT-100-BK-G 3170,160 r90 top
SH-J21 "969102-0000-DA" SNT-100-BK-G 3280,1425 r180 top
SH-J22 "969102-0000-DA" SNT-100-BK-G 130,1820 r180 top
SH-J23 "969102-0000-DA" SNT-100-BK-G 130,1930 r180 top
SH-J24 "969102-0000-DA" SNT-100-BK-G 130,2040 r180 top
SH-J25 "969102-0000-DA" SNT-100-BK-G 780,1830 r180 top
SH-J26 "969102-0000-DA" SNT-100-BK-G 130,1550 r0 top
SH-J27 "969102-0000-DA" SNT-100-BK-G 130,1440 r0 top
SH-J28 "969102-0000-DA" SNT-100-BK-G 130,1330 r0 top
SH-J29 "969102-0000-DA" SNT-100-BK-G 130,1220 r0 top
SH-J30 "969102-0000-DA" SNT-100-BK-G 780,1550 r180 top
SH-J31 "969102-0000-DA" SNT-100-BK-G 780,1700 r180 top
TP2 "RSTn" Keystone5002 3480,690 r90 top
TP3 "DAISY" Keystone5002 3480,580 r90 top
TP4 "SDO" Keystone5002 3480,1020 r90 top
TP5 "SDI" Keystone5002 3480,910 r90 top
TP6 "SCLK" Keystone5002 3480,1240 r90 top
TP7 "CSn" Keystone5002 3480,1130 r90 top
TP8 "ALMn" Keystone5002 3480,800 r90 top
TP9 "REFSELn" Keystone5002 3480,470 r90 top
TP10 "RefOut" Keystone5002 1840,2170 r90 top
TP11 "GND" Keystone5001 600,2450 r90 top
TP12 "5V" Keystone5000 950,710 r90 top
TP13 "HVdd" Keystone5000 2330,1660 r90 top
TP14 "5V5" Keystone5000 1810,500 r90 top
TP15 "HVss" Keystone5000 2330,1450 r90 top
TP16 "AVDD" Keystone5000 600,2300 r90 top
TP17 "DVDD" Keystone5000 2205,750 r90 top
U1 "OPA320AIDBVR" DBV0005A_N 2310,2190 r90 top
U2 "ADS8688DBT" DBT0038A_M 1860,1620 r270 top
U3 "OPA320AIDBVR" SOT23-5P 1520,1620 r0 top
U4 "OPA2209AIDGKR" DGK-8 1110,1880 r90 bottom
U5 "OPA2209AIDGKR" DGK-8 1110,1370 r90 bottom
U6 "TPS7A49XXDGN" DGN-8 1290,580 r0 bottom
U7 "TPS7A49XXDGN" DGN-8 2767.72,1706.38 r0 bottom
U8 "REG710NA-XXX" SOT23-6 2170,520 r0 bottom
U9 "TPS54060DGQ" DGQ-10 2940,250 r90 top locked
U10 "TPS7A30XXDGN" DGN-8 2767.72,1486.38 r0 bottom
U11 "AT24C02B" SO8 3500,168.5 r90 bottom

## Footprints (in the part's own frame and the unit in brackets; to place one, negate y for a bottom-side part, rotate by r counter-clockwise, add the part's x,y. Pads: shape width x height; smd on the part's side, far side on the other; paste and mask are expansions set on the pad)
0402 [mm] "0402 from SM-752 data"
  rect 0.8x0.6 smd: 1(-0.6,0) 2(0.6,0)
  silkscreen extent -1.22,-0.52 1.22,0.52, body extent -0.55,-0.3 0.55,0.3, height 0.6
"0402 - UN" [mm] "0402 from SM-752 data"
  rect 0.8x0.6 smd: 1(-0.6,0) 2(0.6,0)
  silkscreen extent -1.22,-0.52 1.22,0.52
0603 [mm] "0603 from SM-752 data"
  rect 1x0.95 smd: 1(-0.8,0) 2(0.8,0)
  silkscreen extent -1.52,-0.69 1.52,0.69, body extent -0.87,-0.47 0.87,0.47, height 0.85
0603_HV [mil] "Ernesto recommended land pattern.  26 mil between pads."
  rect 30x30 smd: 1(-28,0) 2(28,0)
  silkscreen extent -52,-24 52,24, body extent -34,-19 34,19, height 33
0603M [mm] "0603 from SM-752 data"
  rect 1.2x1.05 smd: 1(-0.9,0) 2(0.9,0)
  silkscreen extent -1.82,-0.84 1.82,0.84, body extent -0.87,-0.47 0.87,0.47, height 0.85
0805_HV [mil] "0805 with 30mil clearance between pads"
  rect 50x63 smd: 1(-40,0) 2(40,0)
  silkscreen extent -74,-40 74,40, body extent -43,-29 43,29, height 43
1206 [mm] "1206 from SM-752 data"
  rect 1.3x1.85 smd: 1(-1.45,0) 2(1.45,0)
  silkscreen extent -2.4,-1.21 2.4,1.21, body extent -1.7,-0.9 1.7,0.9, height 1.35
1210 [mm] "1210 from SM-752 data"
  rect 1.3x2.7 smd: 1(-1.45,0) 2(1.45,0)
  silkscreen extent -2.32,-1.57 2.32,1.57, body extent -1.7,-1.35 1.7,1.35, height 1.35
1280 [mm] "Inductor"
  oct 2.5x4.5 smd: 1(1.75,5.3)
  rect 2.5x4.5 smd: 2(-1.75,5.3) 3(-1.75,-5.3) 4(1.75,-5.3)
  silkscreen extent -6.25,-6.25 6.25,6.25, body extent -6.25,-6.25 6.25,6.25, height 8.6
2220 [mm] "Chip Capacitor, Body 5.7x5.0mm, IPC Medium Density"
  rect 1.6x5.3 smd: 1(-2.6,0) 2(2.6,0)
  silkscreen extent -3.69,-2.94 3.69,2.94, body extent -2.95,-2.62 2.95,2.62, height 1.35
BUMPON_SJ5202 [mil] "3M Hex Bumpon Lt Brn"
  round 1 on Mech4: 0(-135.33,-216.54)
  silkscreen extent -250,-217 250,217, body extent -250,-217 250,217, height 63
CONN_TSM-110-01-T-DV-P [mil]
  rect 36x100 smd mask+2: 1(-450,-110) 2(-450,110) 3(-350,-110) 4(-350,110) 5(-250,-110) 6(-250,110) 7(-150,-110) 8(-150,110) 9(-50,-110) 10(-50,110) 11(50,-110) 12(50,110) 13(150,-110) 14(150,110) 15(250,-110) 16(250,110) 17(350,-110) 18(350,110) 19(450,-110) 20(450,110)
  silkscreen extent -508,-168 508,168, body extent -500,-145 500,145, height 380
DBT0038A_M [mm] "TSSOP, 38-Leads, Body 9.7x4.4mm, Pitch 0.5mm, IPC Low Density"
  oval 2.05x0.3 smd: 1(-2.825,4.5) 2(-2.825,4) 3(-2.825,3.5) 4(-2.825,3) 5(-2.825,2.5) 6(-2.825,2) 7(-2.825,1.5) 8(-2.825,1) 9(-2.825,0.5) 10(-2.825,0) 11(-2.825,-0.5) 12(-2.825,-1) 13(-2.825,-1.5) 14(-2.825,-2) 15(-2.825,-2.5) 16(-2.825,-3) 17(-2.825,-3.5) 18(-2.825,-4) 19(-2.825,-4.5) 20(2.825,-4.5) 21(2.825,-4) 22(2.825,-3.5) 23(2.825,-3) 24(2.825,-2.5) 25(2.825,-2) 26(2.825,-1.5) 27(2.825,-1) 28(2.825,-0.5) 29(2.825,0) 30(2.825,0.5) 31(2.825,1) 32(2.825,1.5) 33(2.825,2) 34(2.825,2.5) 35(2.825,3) 36(2.825,3.5) 37(2.825,4) 38(2.825,4.5)
  silkscreen extent -2.95,-4.9 1.4,5.33, body extent -2.25,-4.9 2.25,4.9, height 1.2
DBV0005A_N [mm] "SOT23, 5-Leads, Body 2.9x1.6mm, Pitch 0.95mm, Lead Span 2.8mm, IPC Medium Density"
  rect 1.1x0.65 smd: 1(-1.2,0.95) 2(-1.2,0) 3(-1.2,-0.95) 4(1.2,-0.95) 5(1.2,0.95)
  silkscreen extent -0.25,-1.55 0.25,1.55, body extent -1.42,-1.46 1.42,1.46, height 1.08
DGK-8 [mm] "SOIC"
  rect 1.85x0.35 smd: 1(-2.5,0.975)
  oval 1.85x0.35 smd: 2(-2.5,0.325) 3(-2.5,-0.325) 4(-2.5,-0.975) 5(2.5,-0.975) 6(2.5,-0.325) 7(2.5,0.325) 8(2.5,0.975)
  silkscreen extent -1.3,-1.5 1.3,1.5, body extent -1.5,-1.5 1.5,1.5, height 1.1
DGN-8 [mm] "TSOP, 8-Leads, Body 3x3mm, Pitch 0.65mm, Thermal Pad 1.89x1.57mm, IPC Low Density"
  oval 2x0.45 smd: 1(-2.15,0.975) 2(-2.15,0.325) 3(-2.15,-0.325) 4(-2.15,-0.975) 5(2.15,-0.975) 6(2.15,-0.325) 7(2.15,0.325) 8(2.15,0.975)
  rect 1.57x1.89 smd: 9(0,0)
  silkscreen extent -2.27,-1.55 0.75,1.87, body extent -1.55,-1.55 1.55,1.55, height 1.1
DGQ-10 [mm] "TSSOP, 10-Leads, Body 3x3mm, Pitch 0.5mm, Thermal Pad 1.88x1.57mm, IPC Medium Density"
  oval 1.7x0.3 smd: 1(-2.05,1) 2(-2.05,0.5) 3(-2.05,0) 4(-2.05,-0.5) 5(-2.05,-1) 6(2.05,-1) 7(2.05,-0.5) 8(2.05,0) 9(2.05,0.5) 10(2.05,1)
  rect 1.57x1.88 smd: 11(0,0)
  silkscreen extent -3.43,-1.55 0.8,1.77, body extent -1.55,-1.55 1.55,1.55, height 1.1
ERF8-025-01-L-D-RA-L [mm] "Samtec, 0.8mm DUAL ROW RIGHT ANGLE SOCKET ASSEMBLY"
  rect 0.5x1.25 smd: 1(9.6,0.94) 2(9.6,-0.94) 3(8.8,0.94) 4(8.8,-0.94) 5(8,0.94) 6(8,-0.94) 7(7.2,0.94) 8(7.2,-0.94) 9(6.4,0.94) 10(6.4,-0.94) 11(5.6,0.94) 12(5.6,-0.94) 13(4.8,0.94) 14(4.8,-0.94) 15(4,0.94) 16(4,-0.94) 17(3.2,0.94) 18(3.2,-0.94) 19(2.4,0.94) 20(2.4,-0.94) 21(1.6,0.94) 22(1.6,-0.94) 23(0.8,0.94) 24(0.8,-0.94) 25(0,0.94) 26(0,-0.94) 27(-0.8,0.94) 28(-0.8,-0.94) 29(-1.6,0.94) 30(-1.6,-0.94) 31(-2.4,0.94) 32(-2.4,-0.94) 33(-3.2,0.94) 34(-3.2,-0.94) 35(-4,0.94) 36(-4,-0.94) 37(-4.8,0.94) 38(-4.8,-0.94) 39(-5.6,0.94) 40(-5.6,-0.94) 41(-6.4,0.94) 42(-6.4,-0.94) 43(-7.2,0.94) 44(-7.2,-0.94) 45(-8,0.94) 46(-8,-0.94) 47(-8.8,0.94) 48(-8.8,-0.94) 49(-9.6,0.94) 50(-9.6,-0.94)
  round 1 hole 1.45 unplated: M1(13.625,3.5) M2(-13.625,3.5)
  round 2.78 hole 1.93: MH1(13.625,-0.85) MH2(-13.625,-0.85)
  round 1.2 hole 0.635: MH3(12.9,5.28) MH4(-12.9,5.28)
  silkscreen extent -16.55,-3.85 16.45,7.5, body extent -16.5,-3.84 16.5,7.51, height 6.42
Fiducial10-20 [mm]
  round 1 smd paste-0.5 mask+0.5: 1(0,0)
  L1_Analog keep-out circle w1.178: c0,0 r0.5
Keystone5000 [mil] "For Keystone 500x miniature loop terminals"
  round 80 hole 40: 1(0,0)
  silkscreen extent -58,-58 58,58, body extent -49,-49 49,49, height 182
Keystone5001 [mil] "For Keystone 500x miniature loop terminals"
  round 80 hole 40: 1(0,0)
  silkscreen extent -58,-58 58,58, body extent -49,-49 49,49, height 182
Keystone5002 [mil] "For Keystone 500x miniature loop terminals"
  round 80 hole 40: 1(0,0)
  silkscreen extent -58,-58 58,58, body extent -49,-49 49,49, height 182
LED_0805 [mil]
  rect 50x60 smd: 1(-45,0) 2(45,0)
  silkscreen extent -35,-80 30,-40
MicroSD [mil] "Micro SD Card"
  body extent -296,-220 296,220, height 65
MOLEX_502570-0893 [mm] "SD Memory Card Connector"
  rect 2.4x1.7 smd: 0(0,-0.9) 0(13.9,-0.9)
  rect 1.5x1.7 smd: 0(4.05,-15.6) 0(12.95,-15.6) 9(6.35,-15.6)
  rect 2.15x1.5 smd: 0(13.9,-10.6)
  rect 0.8x1.5 smd: 1(4.25,-3.75) 2(5.35,-3.75) 3(6.45,-3.75) 4(7.55,-3.75) 5(8.65,-3.75) 6(9.75,-3.75) 7(10.85,-3.75) 8(11.95,-3.75)
  L1_Analog pour cut-out: 13.15,-9.65 13.15,-8.65 13.65,-8.65 13.65,-9.65
  L1_Analog pour cut-out: 10.95,-14.55 10.95,-13.15 13.85,-13.15 13.85,-14.55
  L1_Analog pour cut-out: 7.3,-15.45 7.3,-14.95 8.3,-14.95 8.3,-15.45
  silkscreen extent -0.2,-15.9 14.1,0, body extent 0,-15.7 13.8,-0.2, height 1.81
Net-Tie_10mil [mil] "10mil net tie, no solder mask opening, no solder paste"
  rect 24x24 smd paste-5 mask-5: 1(-17,0) 2(17,0)
  L1_Analog region: -6,12 6,12 6,-12 -6,-12
SMA [mm] "Molded Diode, 2-Leads, Body 4.3x2.6mm, IPC Medium Density, based on OnSemi component dimensions and land pattern"
  rect 2x2 smd: 1(-2,0) 2(2,0)
  silkscreen extent -3.66,-1.57 2.79,1.57, body extent -2.6,-1.3 2.6,1.3, height 2.42
SNT-100-BK-G [mil] "Samtec STEP model"
  round 1 on Mech3: 0(0,0)
  body extent -100,-50 100,50, height 344
SO8 [mil]
  rect 80x26 smd: 1(-95,75) 2(-95,25) 3(-95,-25) 4(-95,-75) 5(94,-75) 6(94,-25) 7(94,25) 8(94,75)
SOD-123 [mm] "On Semi recommended land pattern"
  rect 0.915x1.22 smd: 1(-1.637,0) 2(1.637,0)
  silkscreen extent -2.74,-1.17 2.03,1.17, body extent -1.93,-0.9 1.93,0.9, height 1.35
SOT23-5P [mil]
  rect 42x25 smd: 1(-45,37) 2(-45,0) 3(-45,-37) 4(42,-37) 5(42,37)
SOT23-6 [mil]
  rect 42x25 smd: 1(-45,37) 2(-45,0) 3(-45,-37) 4(42,-37) 5(42,0) 6(42,37)
SOT-23 [mm] "SOT23, 3-Leads, Body 2.9x1.3mm, Pitch 0.95mm, Lead Span 2.5mm, IPC Medium Density"
  rect 1.5x0.6 smd: 1(-0.95,0.95) 2(-0.95,-0.95) 3(0.95,0)
  silkscreen extent 0.2,-1.5 0.7,1.5, body extent -1.16,-1.45 1.21,1.45, height 1
TERM_BLK_ED555-2DS [mil]
  rect 100x100 hole 50: 1(0,0)
  round 100 hole 50: 2(138,0)
  silkscreen extent -93,-161 215,113, body extent -69,-150 207,106, height 323
TERM_BLK_ED555-3DS [mm]
  rect 2.54x2.54 hole 1.27: 1(0,0)
  round 2.54 hole 1.27: 2(3.5,0) 3(7,0)
  silkscreen extent -2.36,-4.09 8.75,2.67, body extent -1.75,-3.83 8.75,2.67, height 8.2
TSW-102-07-G-S [mm] "Samtec 100mil, 1x2, 230 mil above insulator"
  rect 1.65x1.65 hole 1.016 mask+0: 1(-1.27,0)
  round 1.65 hole 1.016 mask+0: 2(1.27,0)
  silkscreen extent -2.54,-1.27 2.54,1.27, body extent -2.54,-1.27 2.54,1.27, height 8.38
TSW-103-07-G-S [mm] "Samtec 100mil, 1x3, 230 mil above insulator"
  rect 1.65x1.65 hole 1.016 mask+0: 1(-2.54,0)
  round 1.65 hole 1.016 mask+0: 2(0,0) 3(2.54,0)
  silkscreen extent -4.83,-1.27 3.81,1.27, body extent -3.81,-1.27 3.81,1.27, height 8.38

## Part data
C1 C2 C3 C6 C51: "CAP, CERM, 0.1uF, 25V, +/-5%, X7R, 0603"
C4 C12 C13 C14 C15 C18 C19 C20 C21 C38 C39 C40 C41 C56 C58: library part "CAP, C1608C0G1H103J080AA", "CAP, 10000pF, 0603, 5%, 50V, C0G"
C5: "CAP, CERM, 10uF, 6.3V, +/-20%, X5R, 0603"
C7 C33 C43 C47 C55 C61 C62: "CAP, CERM, 10uF, 10V, +/-10%, X7R, 0805"
C8: "CAP, CERM, 22uF, 16V, +/-20%, X7R, 1210"
C9 C63: "CAP, CERM, 1uF, 16V, +/-10%, X7R, 0603"
C10: "CAP, CERM, 1uF, 16V, +/-10%, X5R, 0603"
C11: "CAP, CERM, 3000pF, 50V, +/-5%, C0G/NP0, 0603"
C16 C24 C26 C30 C45 C64: "CAP, CERM, 0.1uF, 50V, +/-10%, X7R, 0603"
C17 C22 C27 C28: "CAP, CERM, 2200pF, 50V, +/-5%, C0G/NP0, 0603"
C23 C25 C29 C31: "CAP, CERM, 1000pF, 50V, +/-5%, C0G/NP0, 0402"
C32 C35 C49 C50: "CAP, CERM, 22uF, 25V, +/-10%, X7R, 1210"
C34 C36 C53: "CAP, CERM, 10uF, 25V, +/-10%, X7R, 1206"
C37 C54: "CAP, CERM, 10uF, 35V, +/-10%, X7R, 1206"
C42: "CAP, CERM, 0.22uF, 16V, +/-10%, X7R, 0603"
C44 C46: "CAP, CERM, 2.2uF, 10V, +/-10%, X7R, 0603"
C48: "CAP, CERM, 10uF, 50V, +/-20%, X7R, 2220"
C52: "CAP, CERM, 0.39uF, 16V, +/-10%, X7R, 0603"
C57: "CAP, CERM, 470pF, 50V, +/-10%, X7R, 0603"
C59 C60: "CAP, CERM, 10uF, 35V, +/-10%, X7R, 1210"
D1: "Diode. LED, Red, 2.1-V, 14.2-mcd, 20ma, 0805"
D2 D4: "Diode, Schottky, 60V, 2A, SMA"
D3 D5: "Diode, Zener, 5.6V, 500mW, SOD-123"
D6 D8: "Diode, Zener, 27V, 500mW, SOD-123"
D7: "Diode, Zener, 3.9V, 500mW, SOD-123"
D9 D10: "Diode, Schottky, 30V, 0.2A, SOT-23"
FID1 FID2 FID3 FID4 FID5 FID6: "Fiducial mark.  There is nothing to buy or mount."
H1 H2 H3 H4: "Bumpon, Hex, 0.063mil, 11mm Dia, Lt Brn"
J1 J7: "Header, 100mil, 10x2, SMD"
J2 J3 J4 J5 J6 J15 J16 J17 J21 J22 J23 J24 J25 J26 J27 J28 J29 J30 J31: "Header, TH, 100mil, 2x1, Gold plated, 230 mil above insulator"
J8 J9 J10 J11 J12 J13 J14: "Header, TH, 100mil, 3x1, Gold plated, 230 mil above insulator"
J18: "Terminal Block, 6A, 3.5mm Pitch, 3-Pos, TH"
J19: "Receptacle, Micro High Speed Socket Strip, 0.8mm, 25x2, R/A, SMT"
J20: library part Molex_502570-0893, "SD Memory Card Connector"
J32 J33: "Terminal Block, 6A, 3.5mm Pitch, 2-Pos, TH"
L1: library part "Wurth 744870471"
NT1: "Single point connection between nets."
Q1: library part "BC847CLT1G, ON Semiconductor", "Transistor, NPN, 45V, 0.1A, SOT-23"
R1 R79 R80 R81 R82 R83 R84 R85: "RES, 10.0k ohm, 1%, 0.063W, 0402"
R2 R3 R5 R6 R7 R8 R9 R10 R14 R16 R86 R87 R88 R89 R90 R91 R93: "RES, 49.9 ohm, 1%, 0.063W, 0402"
R4 R33 R39 R47 R49 R61 R69 R77 R78 R92 R97 R101 R104 R105 R106 R108: "RES, 0 ohm, 5%, 0.063W, 0402"
R11 R21 R22 R74 R76: "RES, 10.0Meg ohm, 1%, 0.063W, 0402"
R12: "RES, 1.0k ohm, 5%, 0.125W, 0805"
R13 R15 R18: "RES, 47.0k ohm, 1%, 0.1W, 0603"
R17: "RES, 220k ohm, 5%, 0.063W, 0402"
R19: "RES, 100 ohm, 1%, 0.1W, 0603"
R20: "RES, 100k ohm, 1%, 0.063W, 0402"
R23 R24 R25 R26 R27 R28 R29 R30 R31 R32 R34 R35 R37 R38 R40 R41: "RES, 357 ohm, 1%, 0.063W, 0402"
R36 R44 R48 R52 R94 R95 R96 R98 R99 R100 R102 R103 R107: library part Uninst_Res_0402, "Resistor, Uninstalled"
R42 R46 R50 R54: "RES, 3.57k ohm, 1%, 0.063W, 0402"
R43 R45 R51 R53: "RES, 6.65k ohm, 1%, 0.063W, 0402"
R55: "RES, 576k ohm, 1%, 0.063W, 0402"
R56 R71: "RES, 232k ohm, 1%, 0.063W, 0402"
R57: "RES, 182k ohm, 1%, 0.063W, 0402"
R58 R60 R62 R72: "RES, 499k ohm, 1%, 0.063W, 0402"
R59 R73: "RES, 20k ohm, 5%, 0.063W, 0402"
R63: "RES, 33k ohm, 5%, 0.063W, 0402"
R64 R75: "RES, 82k ohm, 5%, 0.063W, 0402"
R65: "RES, 15k ohm, 5%, 0.063W, 0402"
R66: "RES, 1.1k ohm, 5%, 0.063W, 0402"
R67: "RES, 44.2k ohm, 1%, 0.063W, 0402"
R68: "RES, 412k ohm, 1%, 0.063W, 0402"
R70: "RES, 20.5k ohm, 1%, 0.063W, 0402"
SD1: library part "SD Card", "SanDisk MicroSD Card, 2GB"
SH-J2 SH-J3 SH-J4 SH-J5 SH-J6 SH-J8 SH-J9 SH-J10 SH-J11 SH-J12 SH-J13 SH-J14 SH-J15 SH-J16 SH-J17 SH-J21 SH-J22 SH-J23 SH-J24 SH-J25 SH-J26 SH-J27 SH-J28 SH-J29 SH-J30 SH-J31: "Shunt, 100mil, Gold plated, Black"
TP2 TP3 TP4 TP5 TP6 TP7 TP8 TP9 TP10: library part 5002, "Test Point, Miniature, White, TH"
TP11: library part 5001, "Test Point, Miniature, Black, TH"
TP12 TP13 TP14 TP15 TP16 TP17: library part 5000, "Test Point, Miniature, Red, TH"
U1 U3: library part OPA376AIDBV, "Op Amp, Precision, 20MHz, 0.9pA, Low-Noise, RRIO, CMOS, with Shutdown"
U2: "16 bit 400KSPS 8 Channel SAR ADC"
U4 U5: "OpAmp, Low Noise, Low Power, 36V"
U6 U7: "IC, VIN 3V to 35V, 150mA, Ultralow Noise, High-PSRR, LDO Regulator"
U8: "IC, SWITCHED CAP, BUCK BOOST CONVERTER 1.8V to 5.5V in 65uA"
U9: "Buck Inverting Buck-Boost Step Down Regulator with 3.5 to 60 V Input and 0.8 to 58 V Output, -40 to 150 degC, 10-Pin MSOP-PowerPAD (DGQ), Green (RoHS & no Sb/Br)"
U10: "IC, -3V to -36V, -200mA, Ultralow Noise, High-PSRR LDO Negative Linear Regulator"
U11: "IC, 2K, Serial EEPROM"

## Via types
v1: diameter 24, hole 12, L1_Analog to L6_Digital, tented both sides, 318 vias

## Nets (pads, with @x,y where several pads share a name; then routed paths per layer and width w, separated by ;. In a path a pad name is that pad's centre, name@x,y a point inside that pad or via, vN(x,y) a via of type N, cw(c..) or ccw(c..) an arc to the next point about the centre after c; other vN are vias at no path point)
3V3_LP: J1.1 R108.1 | length 1387.2
  L1_Analog w36: J1.1@3140,1300 v1(3210,1300)
  L3_AnalogPower w36: v1(3210,1300) 3140,1300 3135.87,1295.87 3131,1295.87 3104.13,1269 3104.13,1264.13 3100,1260 3100,430 3200,330 v1(3290,330)
  L6_Digital w25: v1(3290,330) 3370,330 R108.1@3370,283.62
3V3_SDCC: J19.13 R78.1 | length 2739.7
  L1_Analog w20: J19.13@3837.01,661.02 3898.98,661.02 v1(3900,660)
  L3_AnalogPower w40: v1(1960,190) 2000,150 2620,150 2743,27 3757,27 3870,140 3870,390 3830,430 3830,590 v1(3900,660)
  L6_Digital w20: R78.1@1873.62,190 v1(1960,190)
5V: C33.1 C38.1 R55.2 R77.2 TP12.1 U6.1 | length 712.3
  L6_Digital w17.72: C38.1@1056.38,557.87 1048.5,550 1083.94,514.57 1144.57,514.57 1171.61,541.61 U6.1@1205.35,541.61
  L6_Digital w25: C38.1@1048.5,550 980,550 C33.1@970,560 970,690 TP12.1@950,710 1010,710 1050,750 1050,780 1080,810 R77.2@1116.38,810 ; C38.1@1056.38,557.87 R55.2@1056.38,610
5V5: C43.1 C44.1 J13.3 TP14.1 U8.1 | length 556.2
  L6_Digital w25: J13.3@1820,730 1820,510 TP14.1@1810,500 2020,500 C43.1@2030,490 2037,483 U8.1@2125,483
5V_SDCC: J19.14 R105.1 | length 109.8
  L1_Analog w19.68: v1(3700,660) 3701.02,661.02 J19.14@3762.99,661.02
  L6_Digital w19.68: R105.1@3653.62,660 v1(3700,660)
A0+: J7.6 J8.3 J25.2 | length 812
  L1_Analog w12.52: J7.6@580,1830 J25.2@720,1830 ; J25.2@730,1830 J25.2@720,1830 ; J8.3@1320,1990 921.42,1990 ccw(c921.42,1890) 850.71,1960.71 J25.2@720,1830
A0-: J7.5 J22.1 R34.1 | length 1538
  L1_Analog w12.52: J22.1@180,1820 190,1830 J7.5@360,1830 430,1830 455,1805 ccw(c515.36,1865.36) 455.04,1804.96 ccw(c515.36,1865.36) 515.36,1780 928.58,1780 ccw(c928.58,1880) 999.29,1809.29 1100.71,1910.71 cw(c1171.42,1840) 1171.42,1940 1340,1940 1370.57,1970.57 1370.57,1971.63 1384.47,1985.53 1384.72,1985.28 1389.22,1989.79 1389.79,1989.79 1420,2020 cw(c1468.28,1971.72) 1468.28,2040 1490,2040 cw(c1490,1967.57) 1541.21,2018.79 1560,2000 R34.1@1560,1973.62
A1+: J7.8 J10.3 J31.2 | length 786.6
  L1_Analog w12.52: J7.8@580,1730 660,1730 cw(c660,1633.43) 728.28,1701.72 J31.2@730,1700 760,1730 cw(c808.28,1681.72) 808.28,1750 1020,1750 cw(c1020,1653.43) 1088.28,1721.72 1100.71,1709.29 ccw(c1171.42,1780) 1100.77,1709.23 ccw(c1171.42,1780) 1171.42,1680 J10.3@1320,1680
